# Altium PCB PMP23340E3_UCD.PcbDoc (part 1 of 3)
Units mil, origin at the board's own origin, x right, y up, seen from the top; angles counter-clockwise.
Board outline 2299.21 x 1157.48 mil, 14 copper layers (Top Layer, Layer 1, Layer 2, Layer 3, Layer 4, Layer 5, Layer 6, Layer 7, Layer 8, Layer 9, Layer 10, Layer 11, Layer 12, Bottom Layer), stack 130 mil thick; 242 components, 71 nets, 1021 pads, 321 vias.
Unrouted connection lines stored in the file: 1.
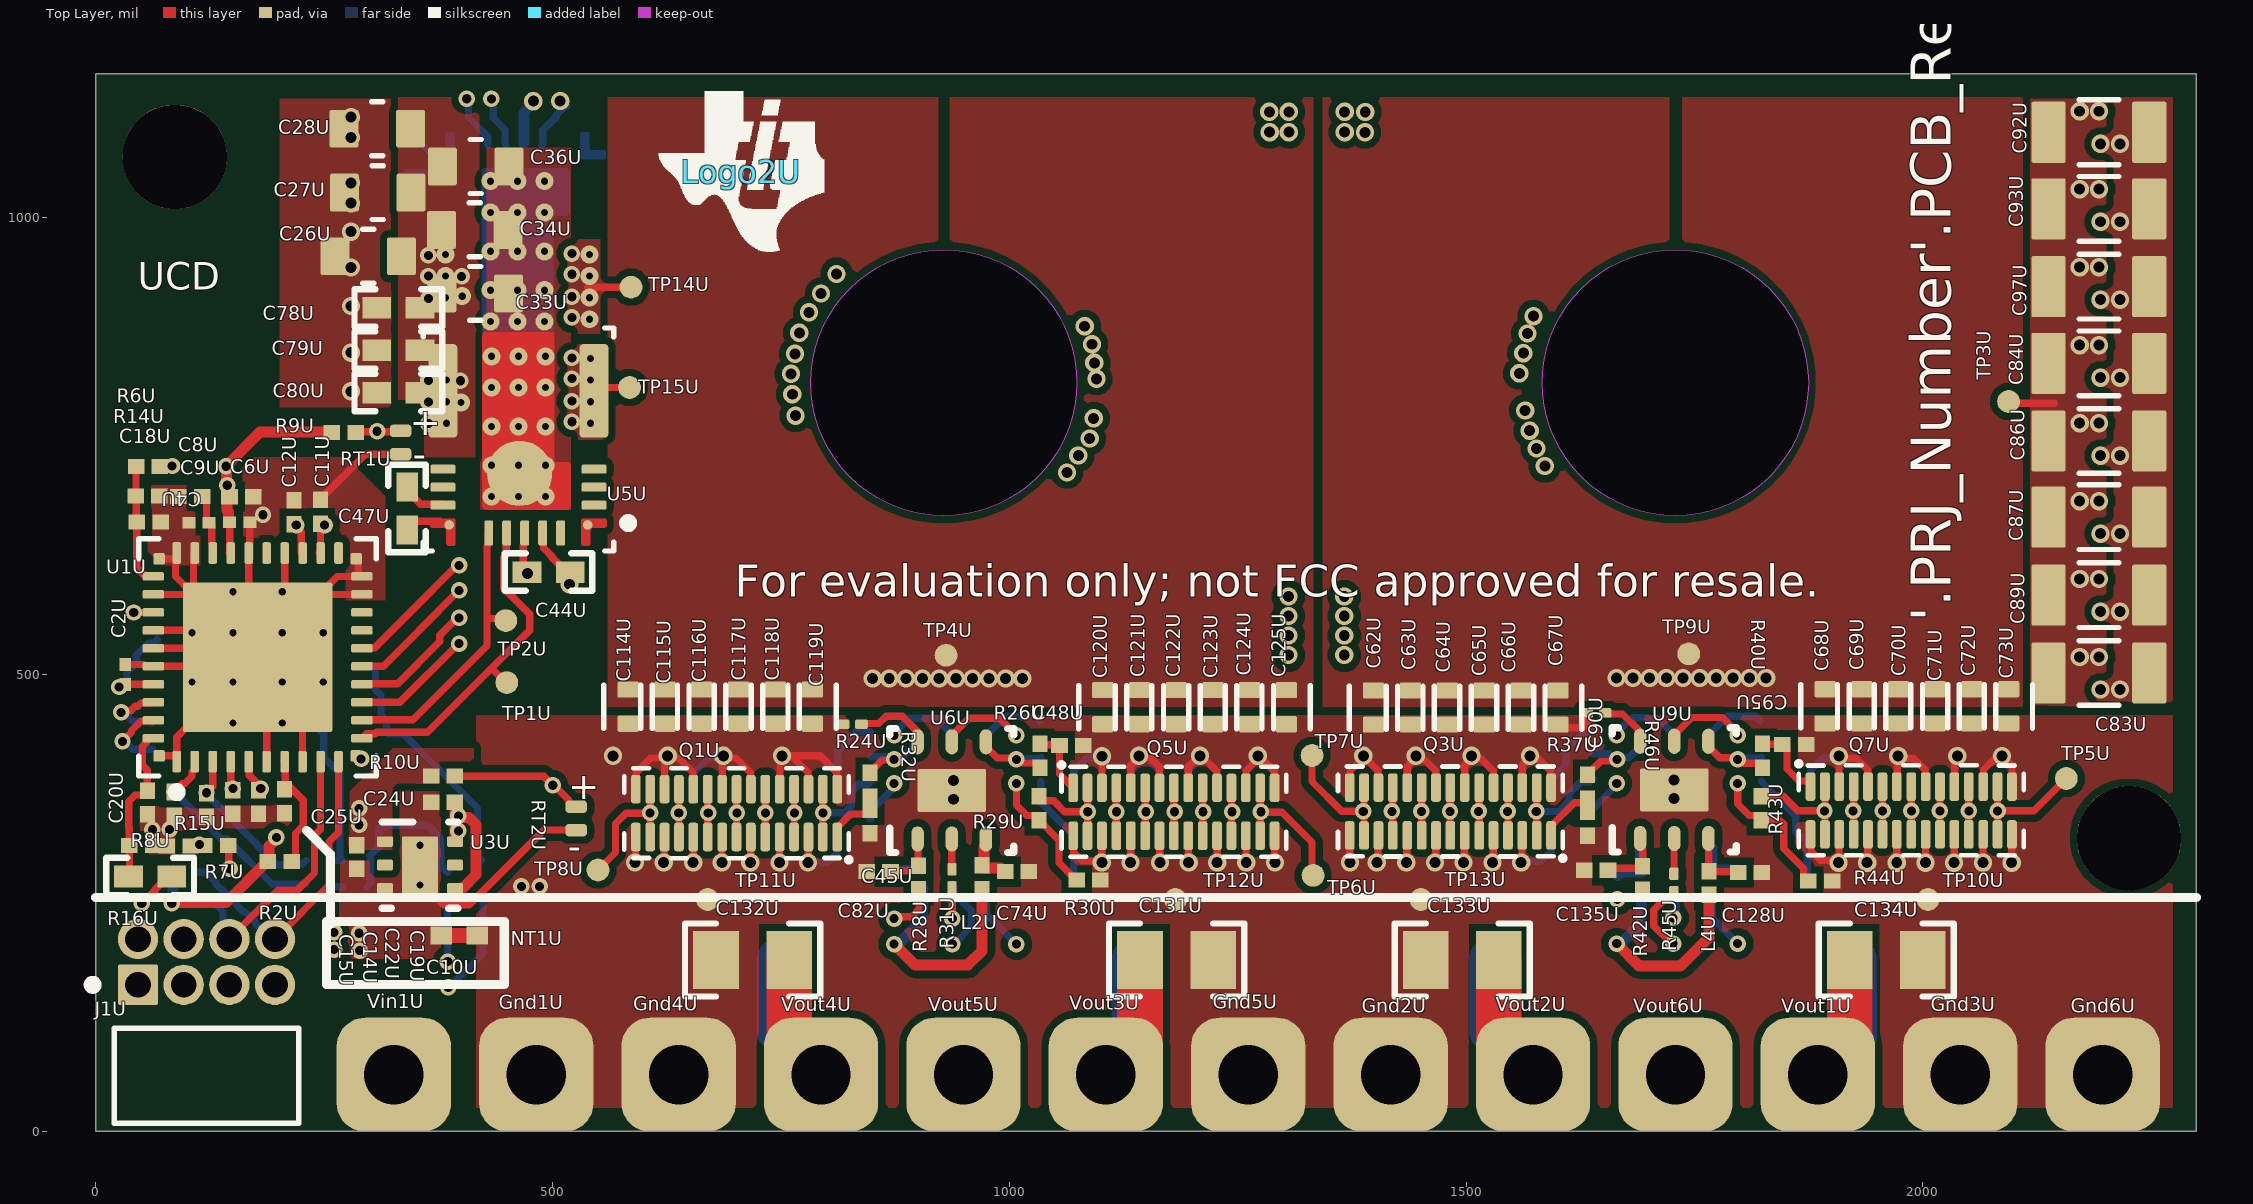
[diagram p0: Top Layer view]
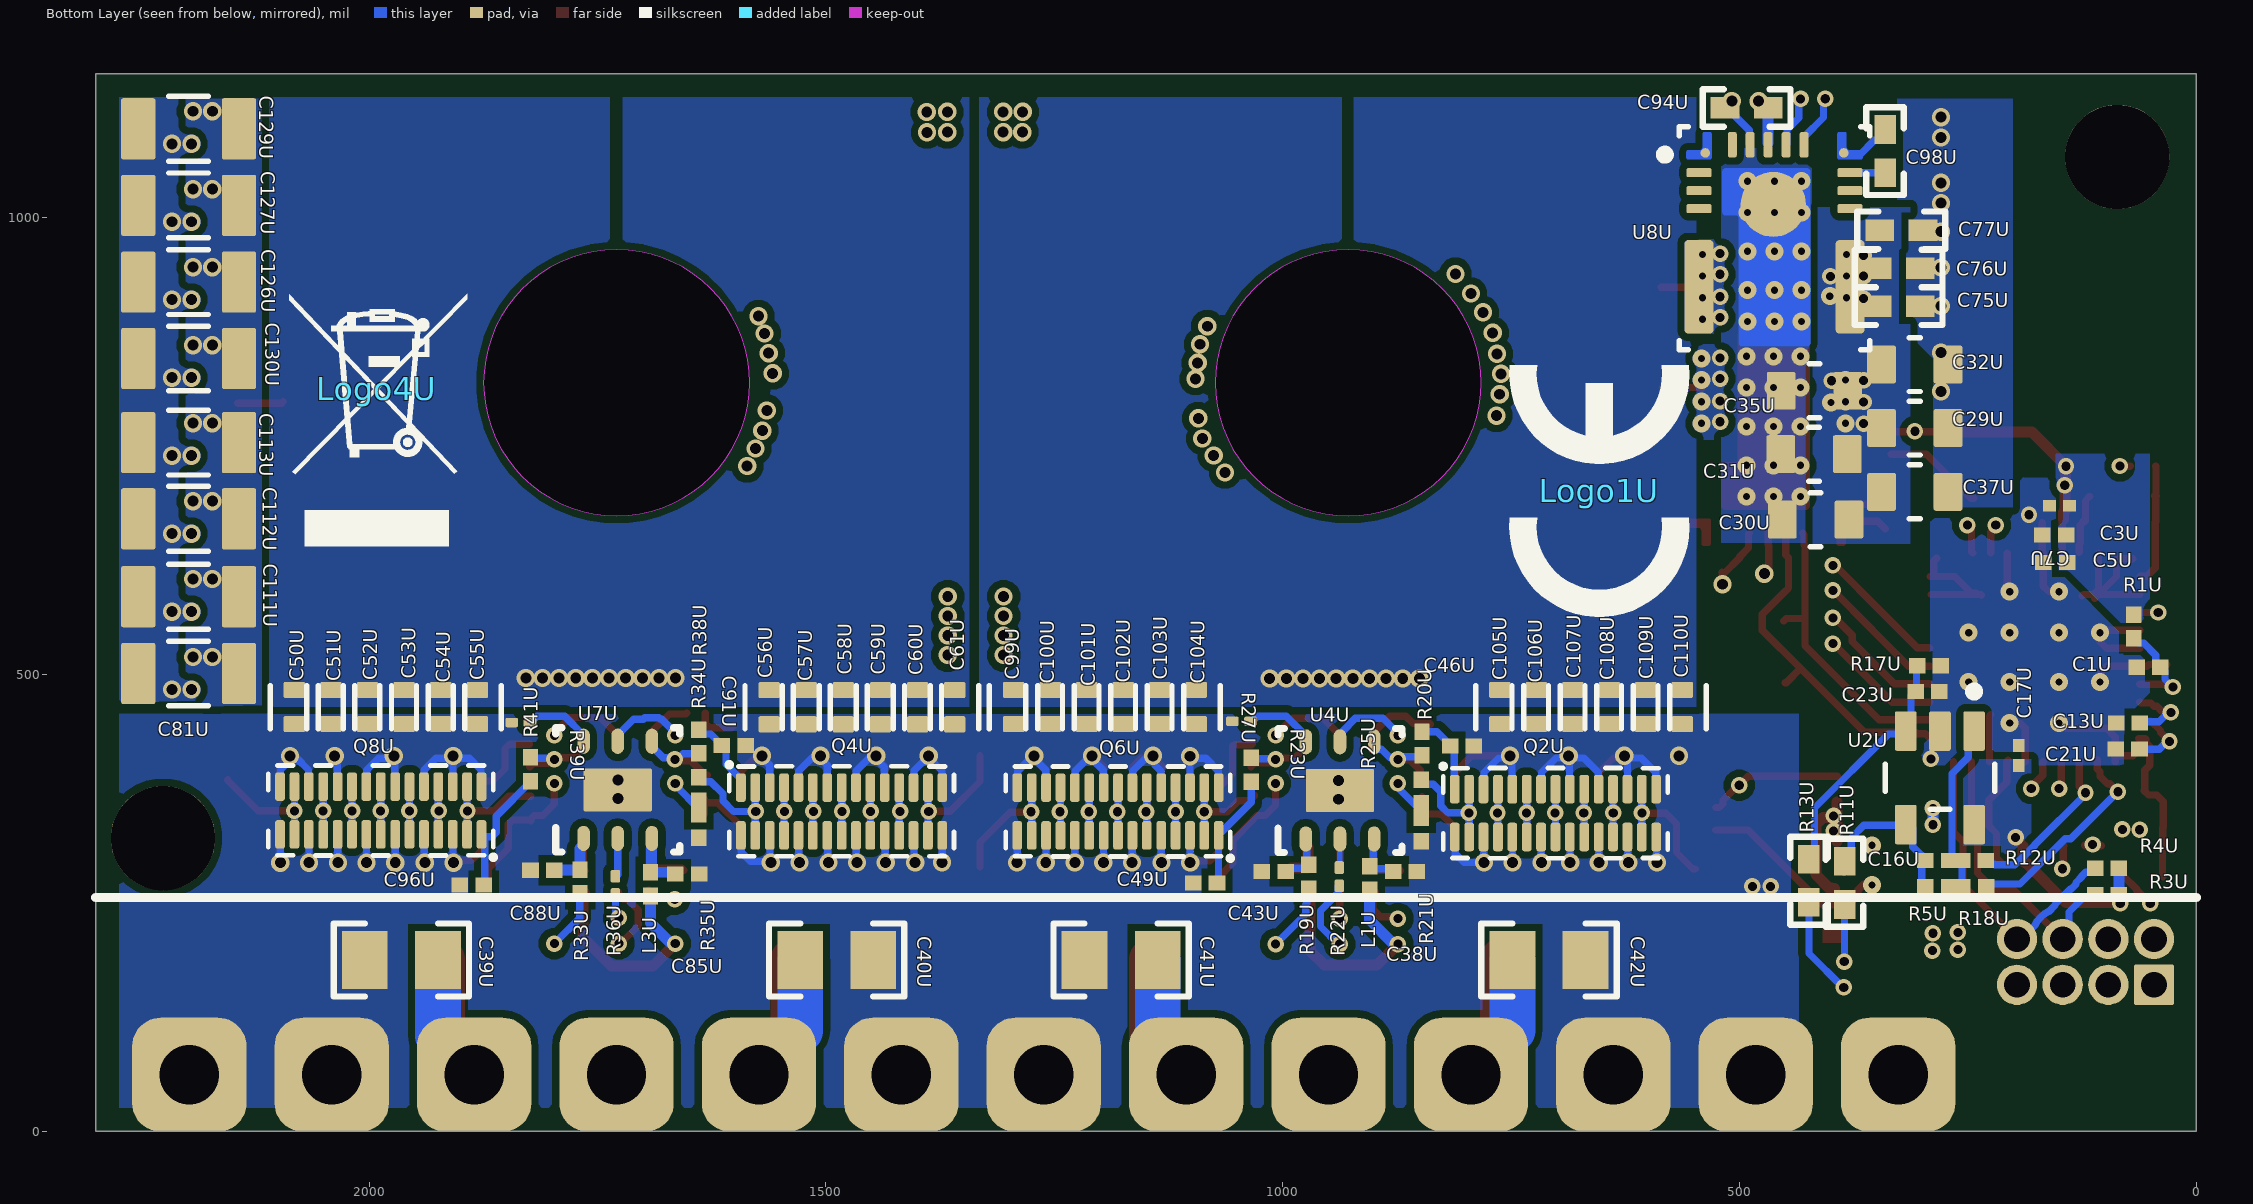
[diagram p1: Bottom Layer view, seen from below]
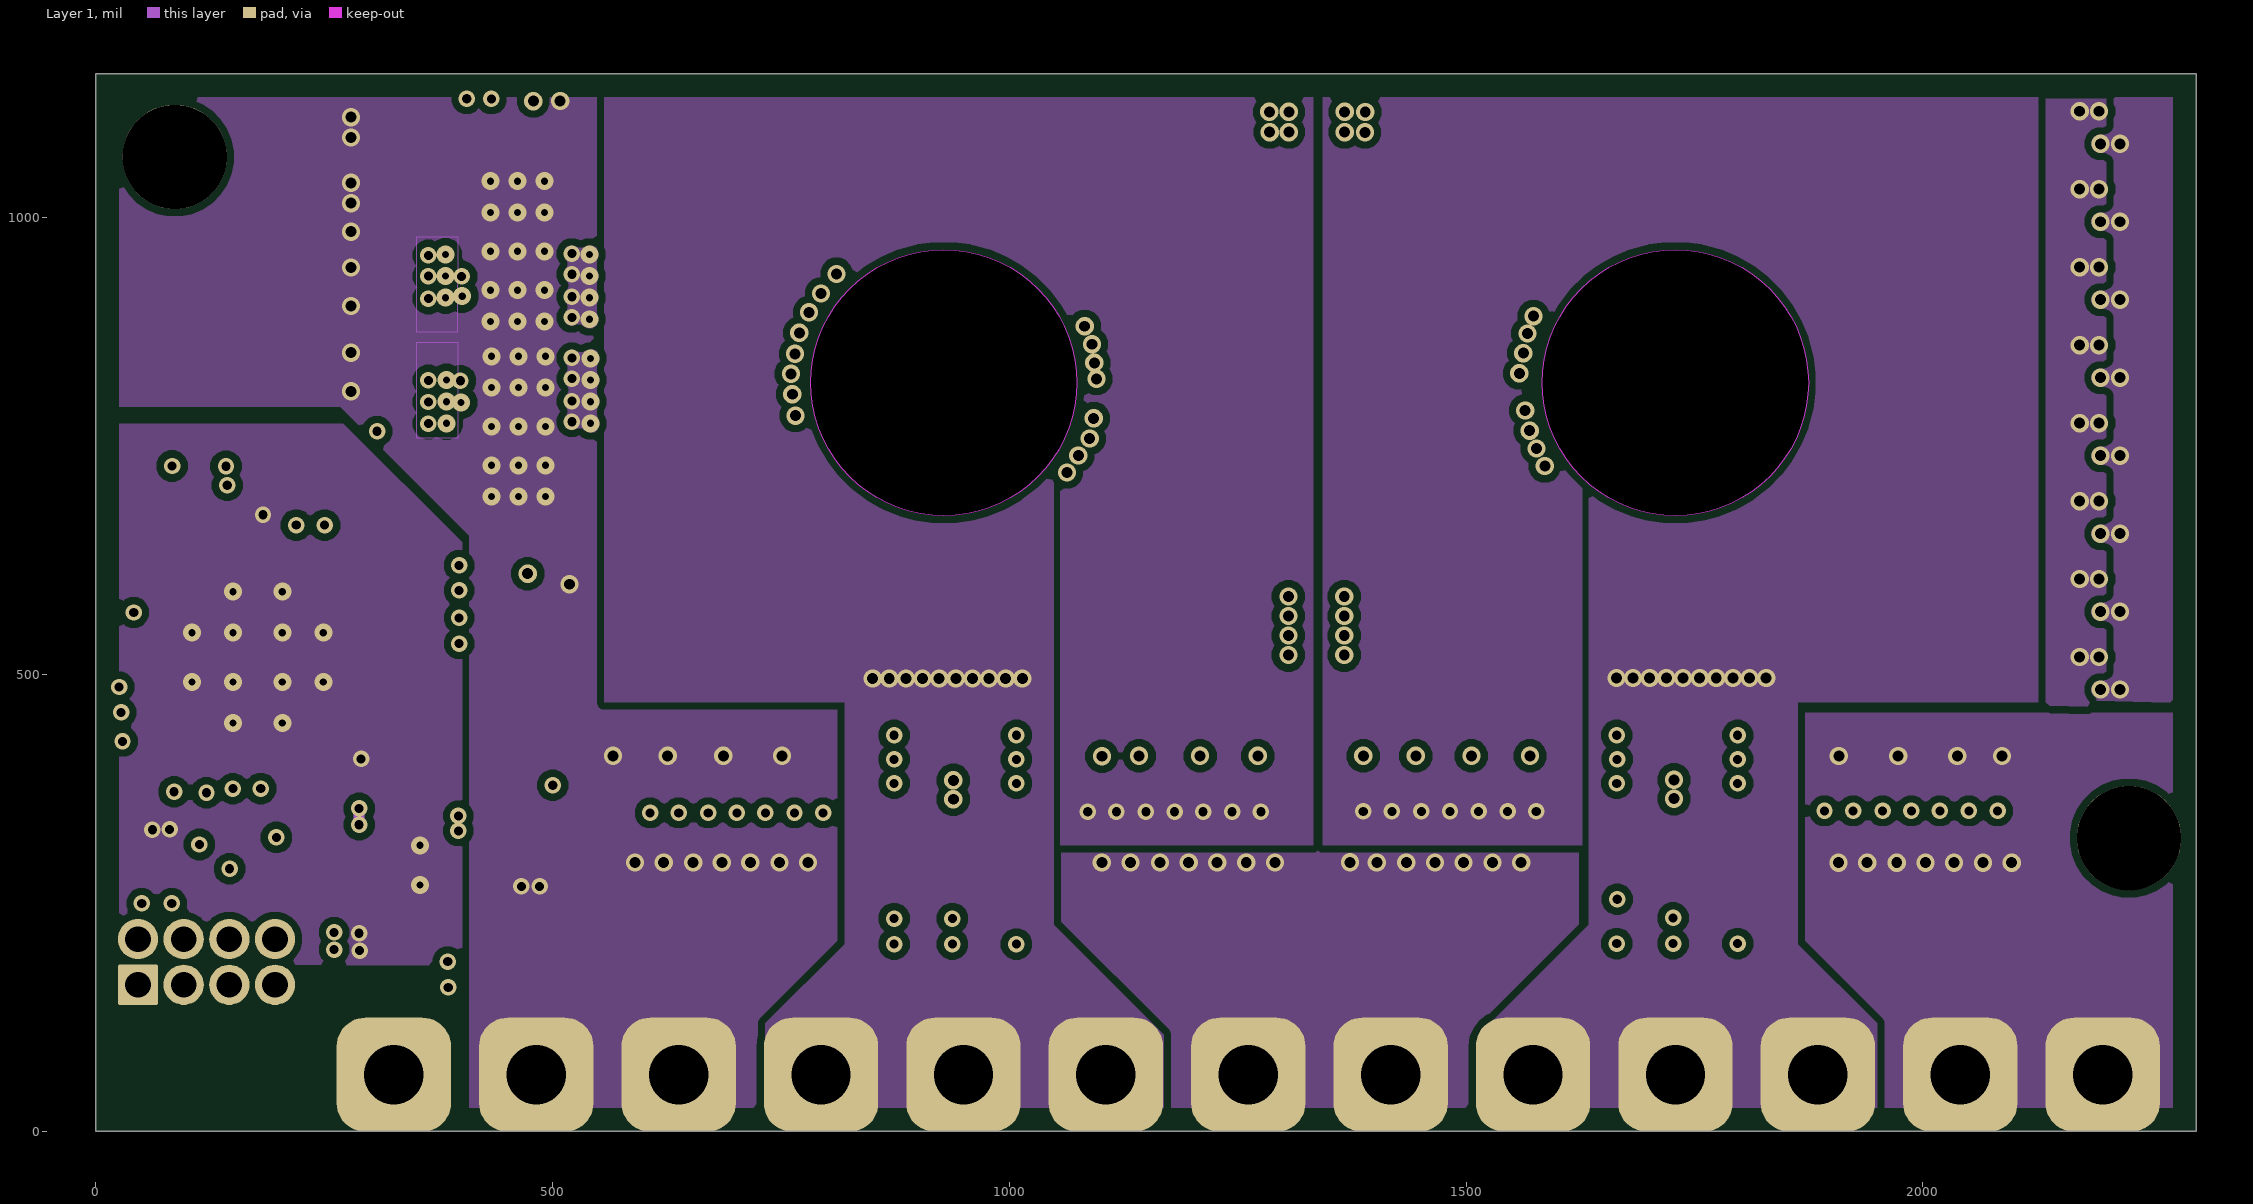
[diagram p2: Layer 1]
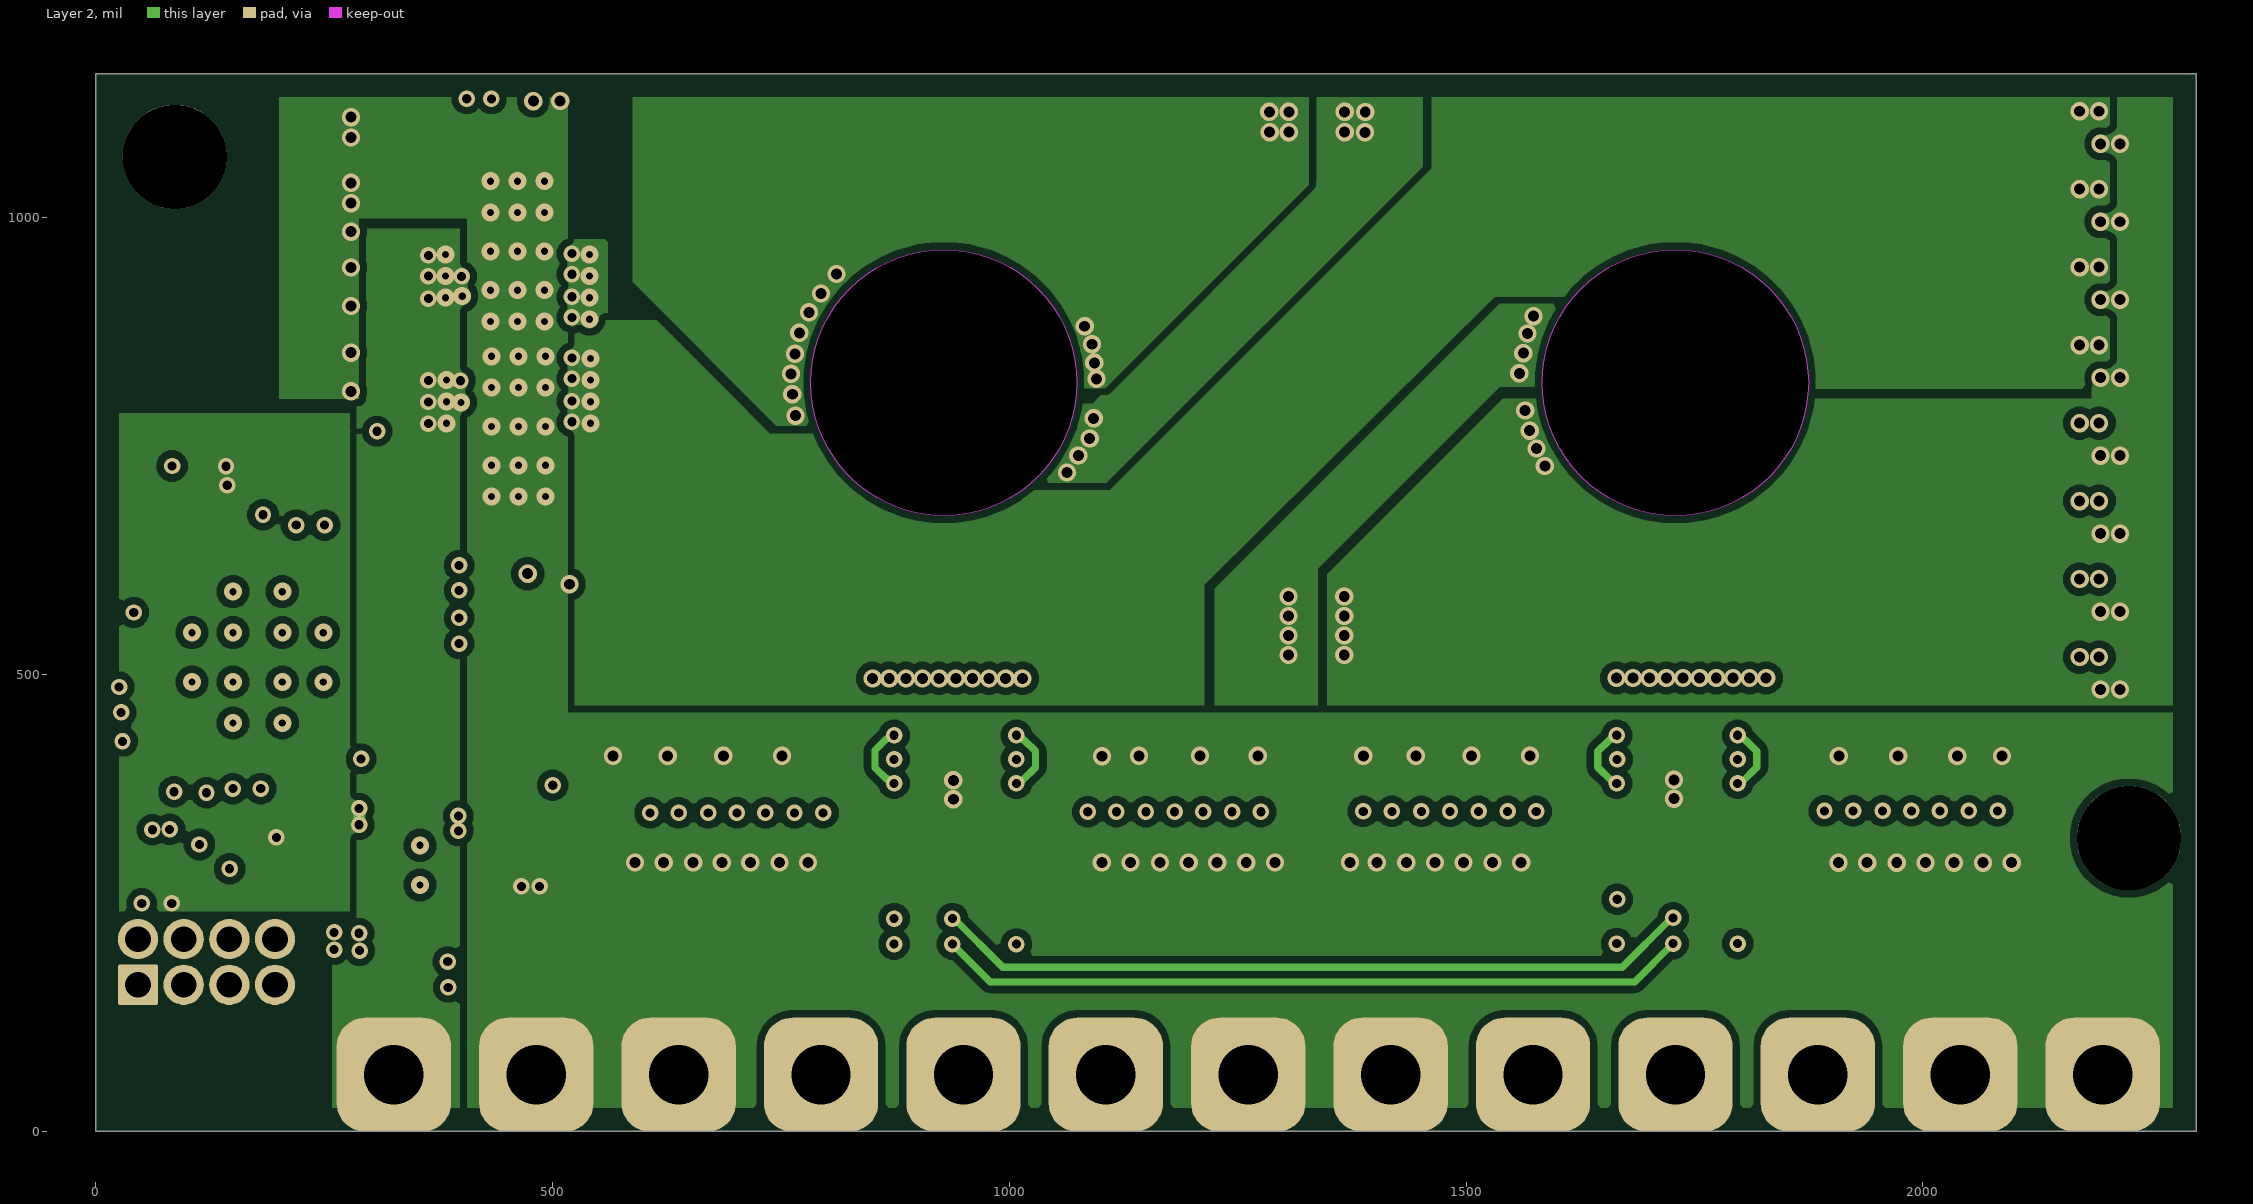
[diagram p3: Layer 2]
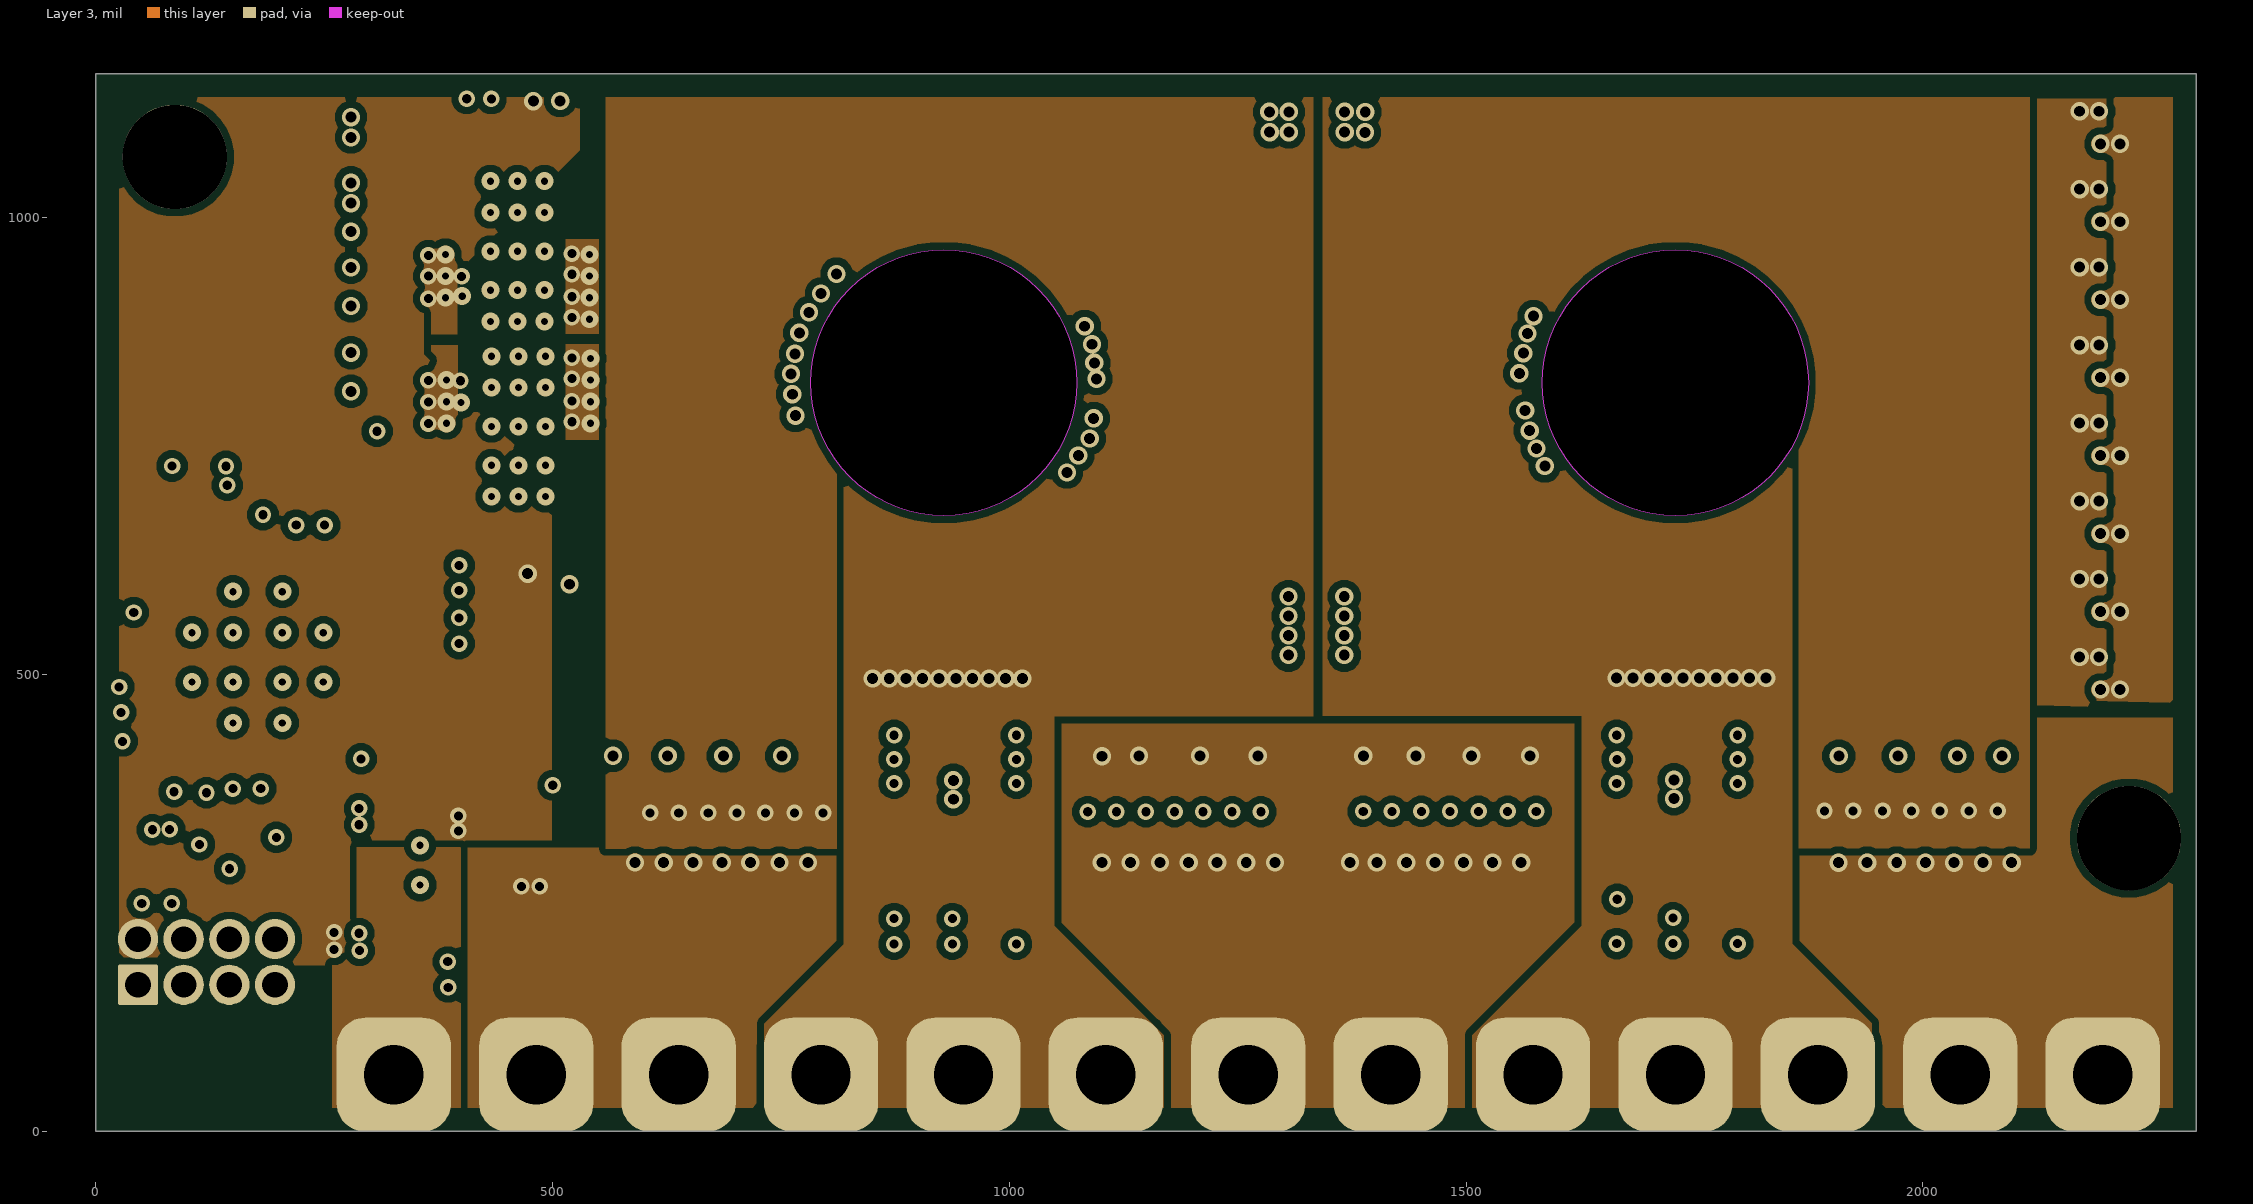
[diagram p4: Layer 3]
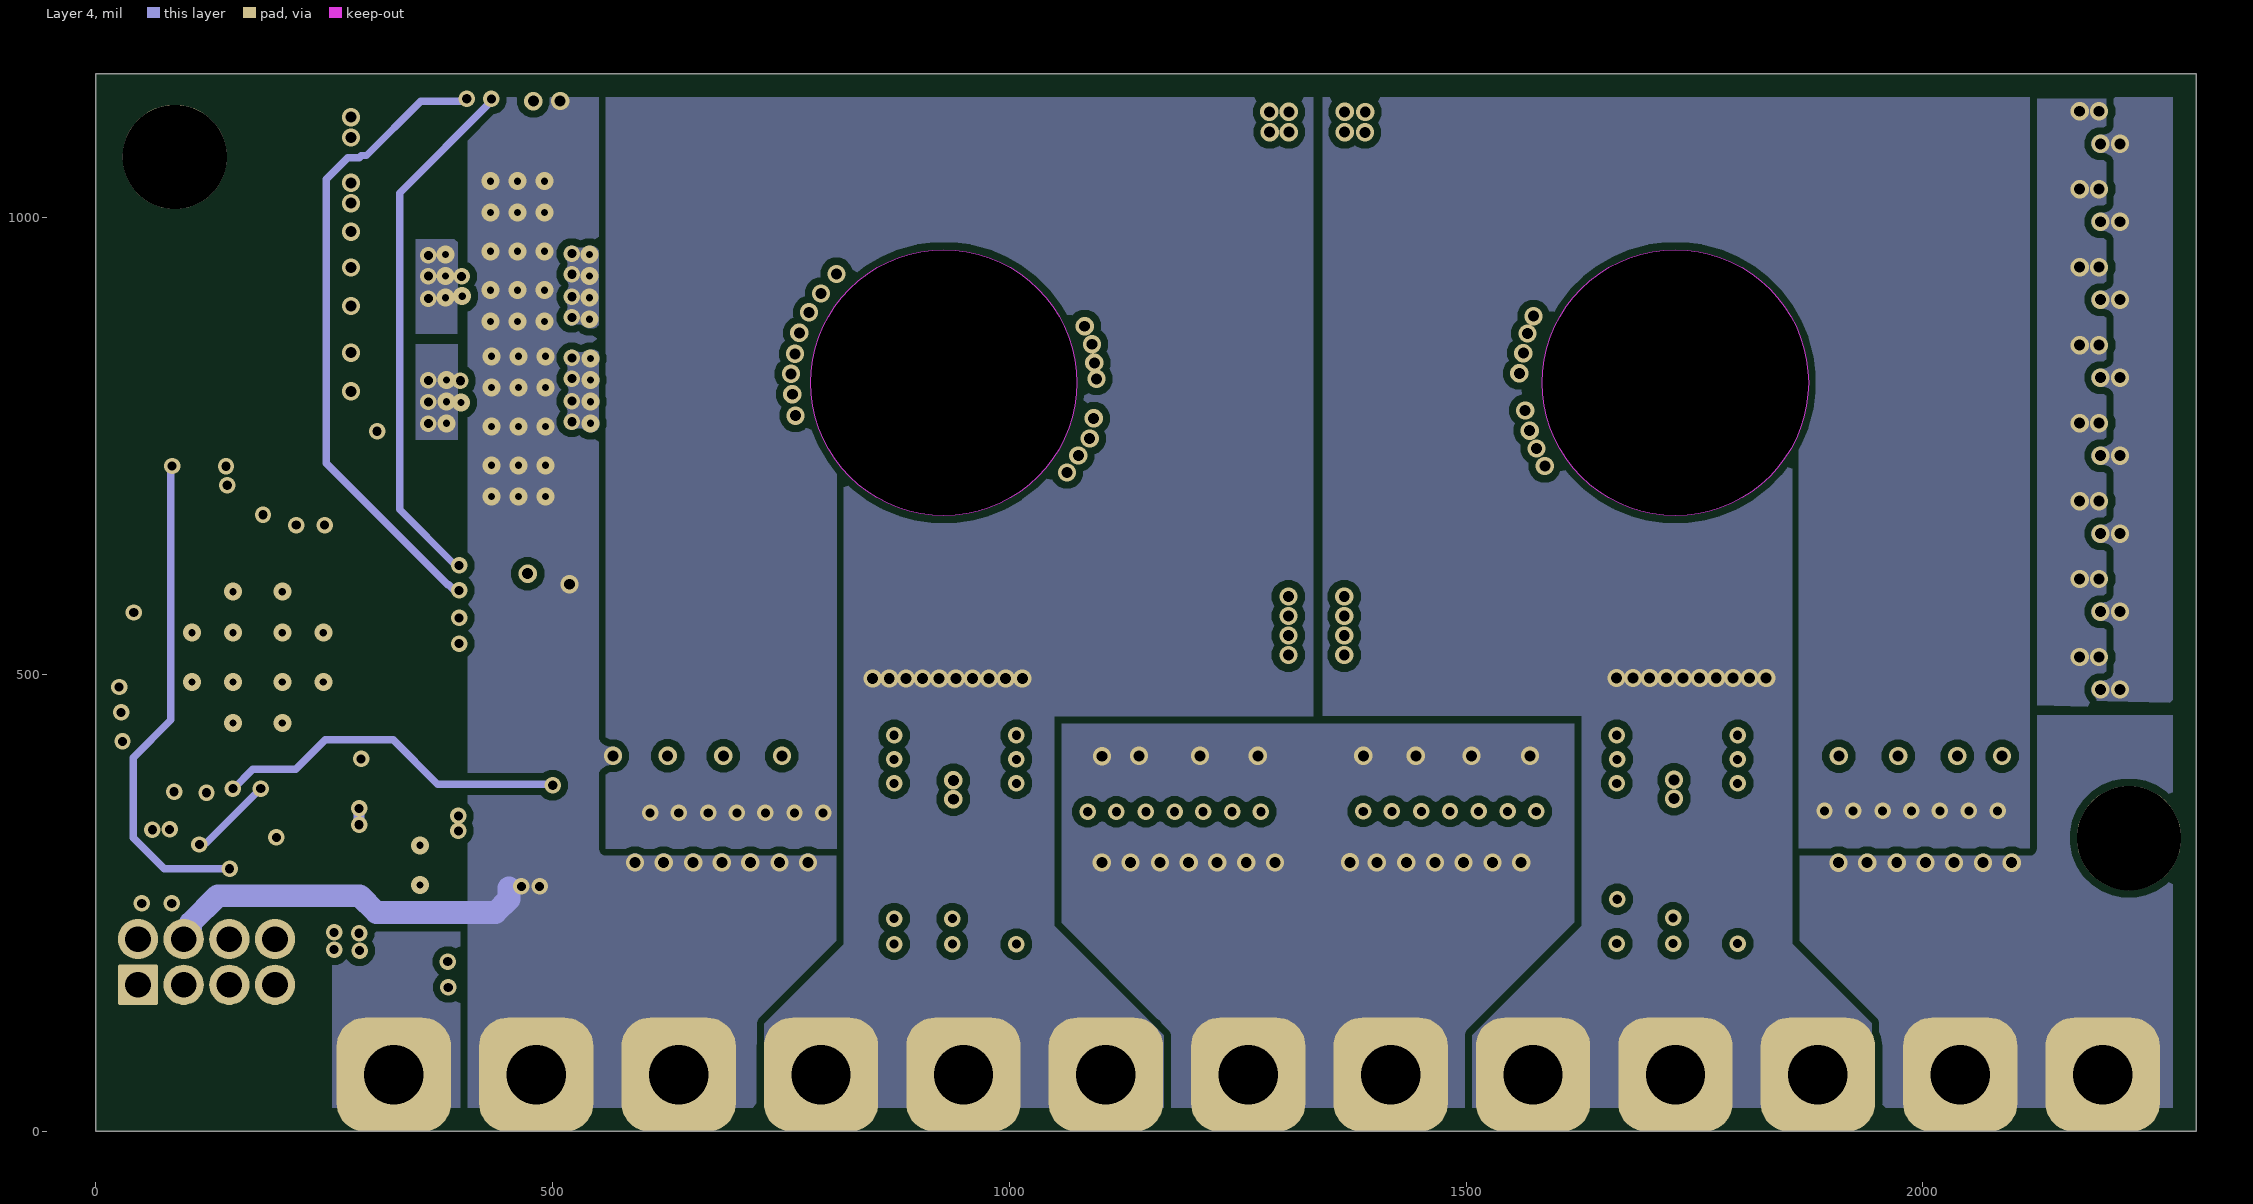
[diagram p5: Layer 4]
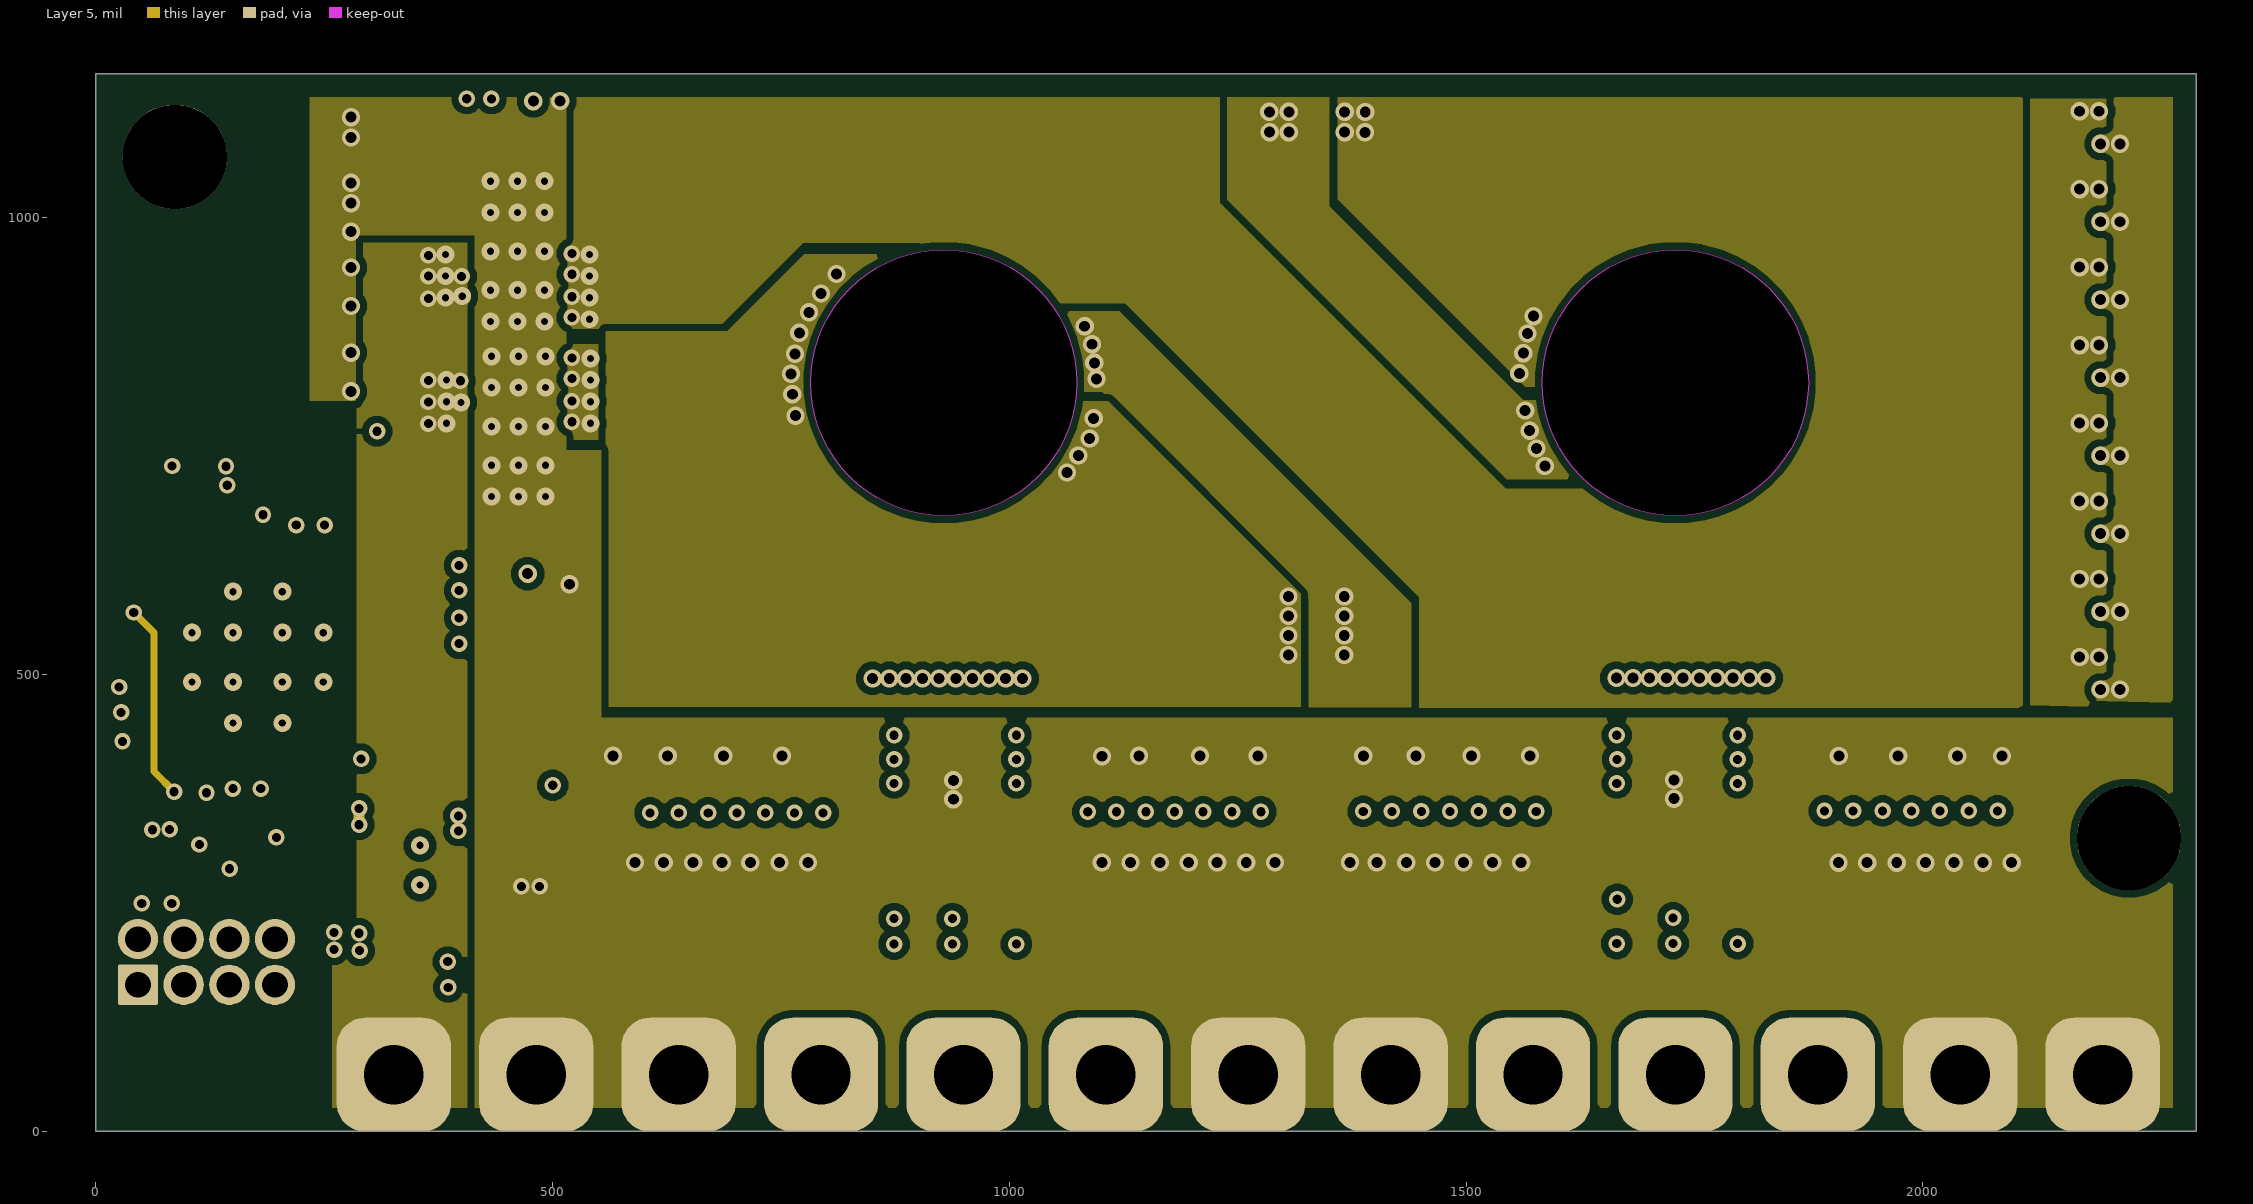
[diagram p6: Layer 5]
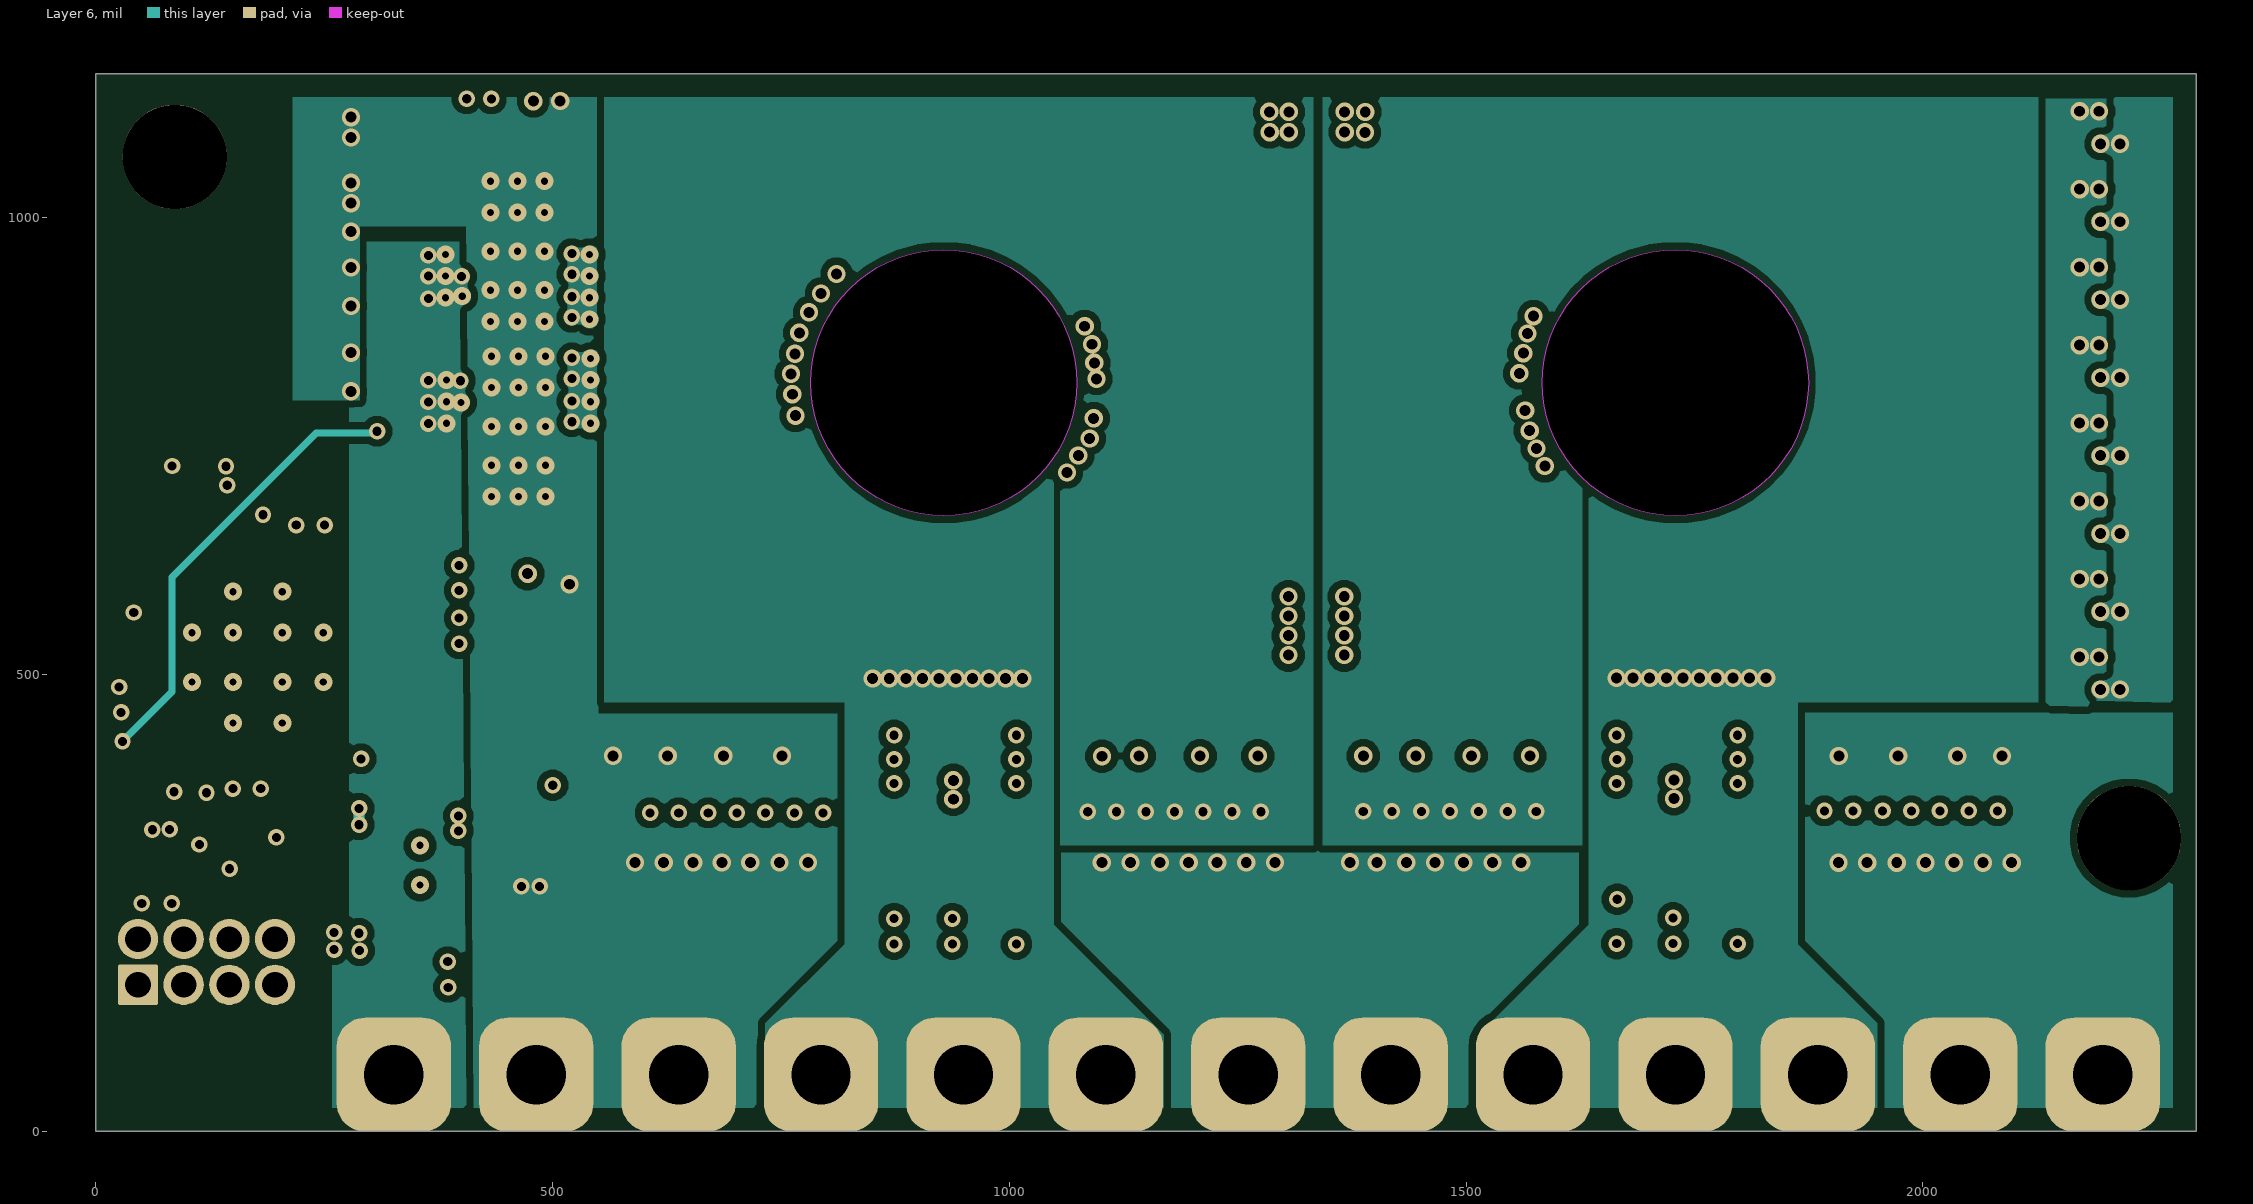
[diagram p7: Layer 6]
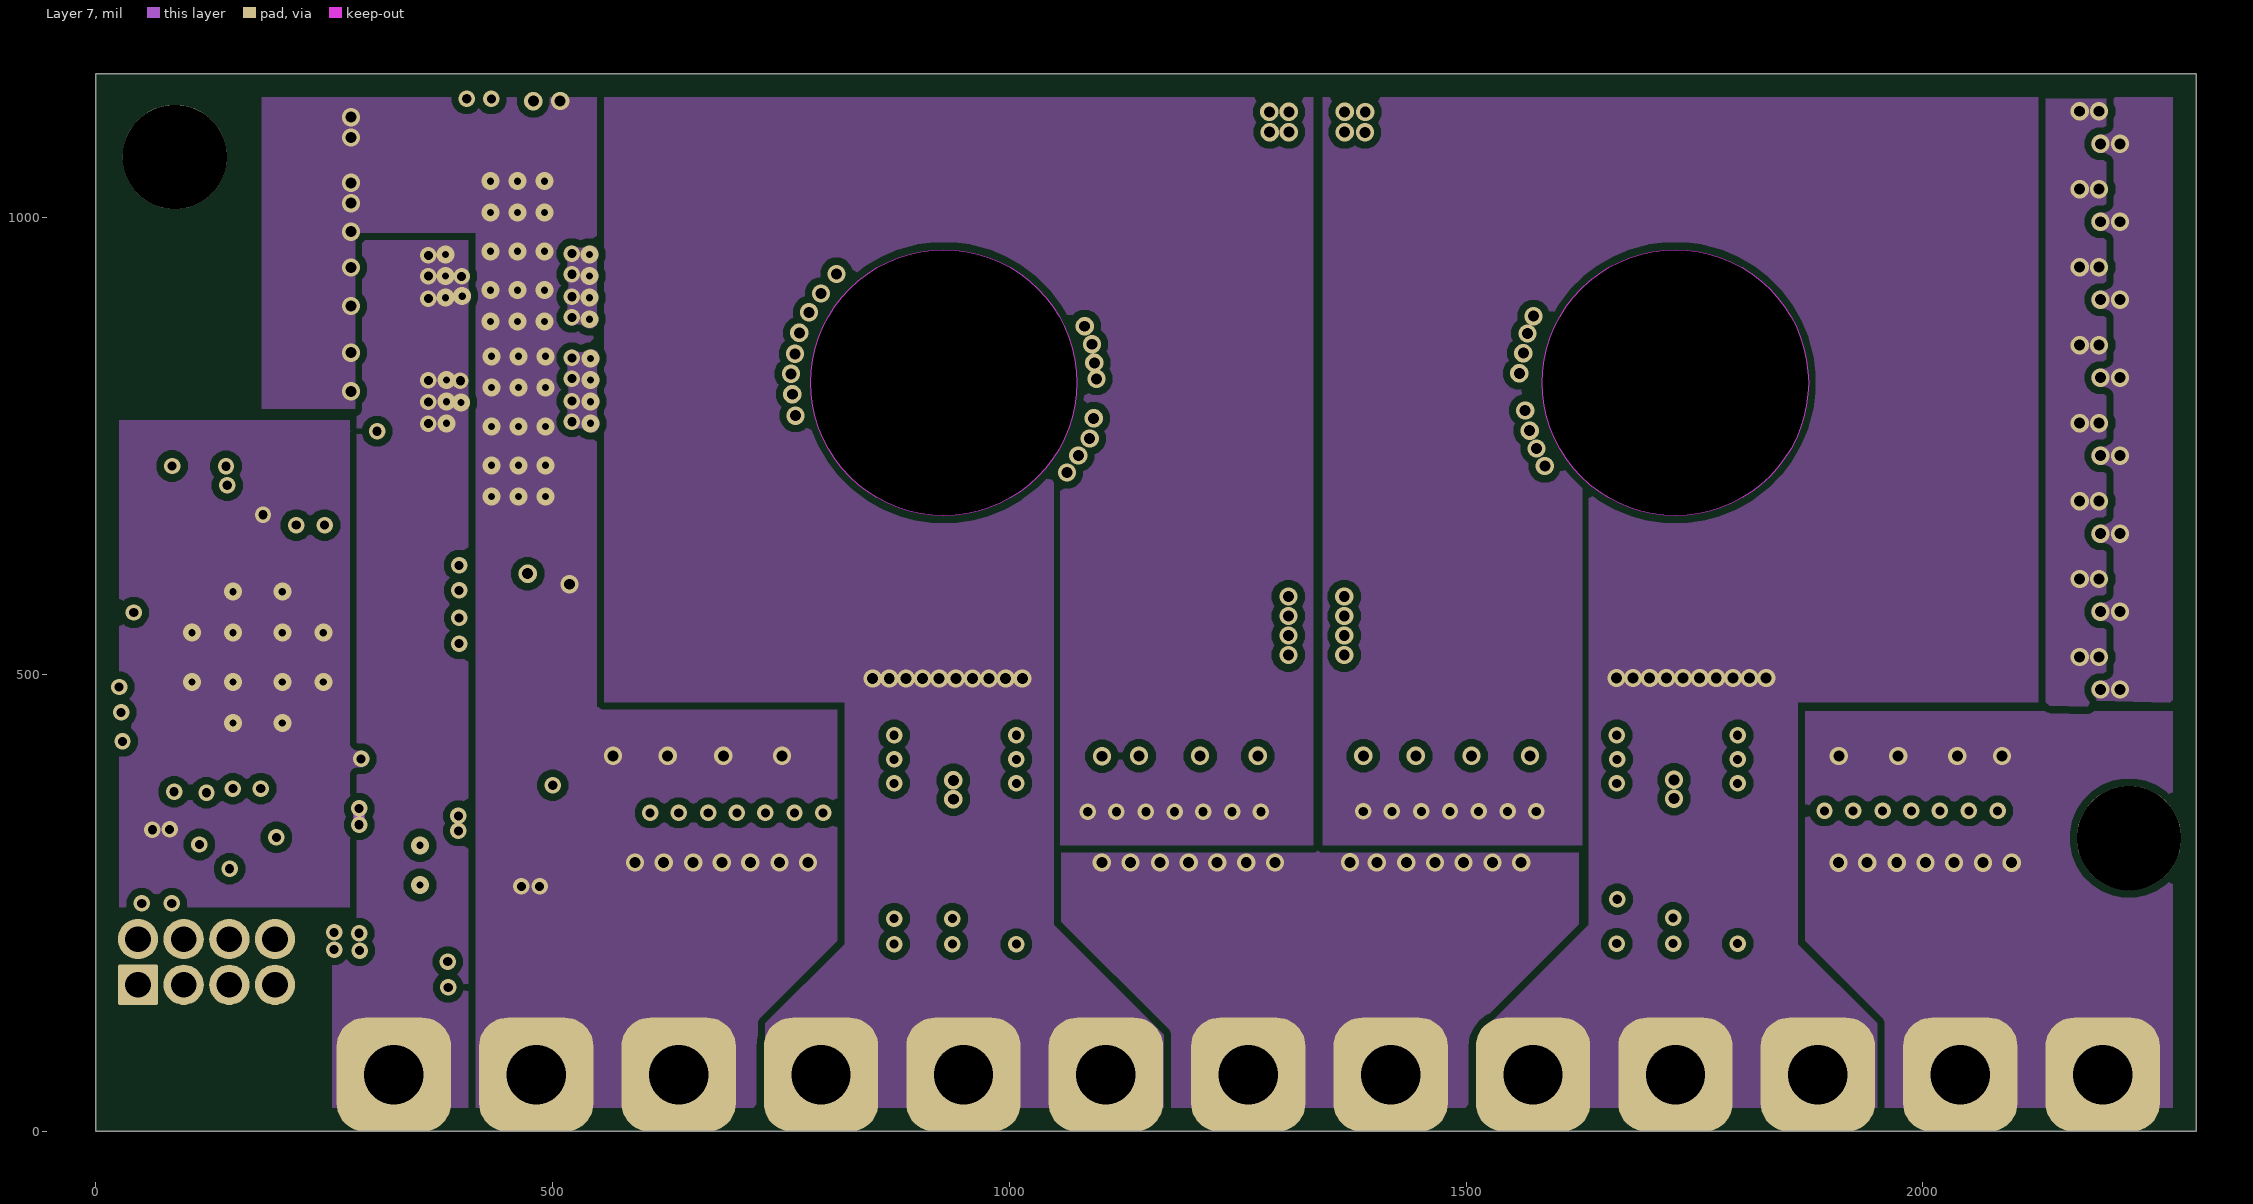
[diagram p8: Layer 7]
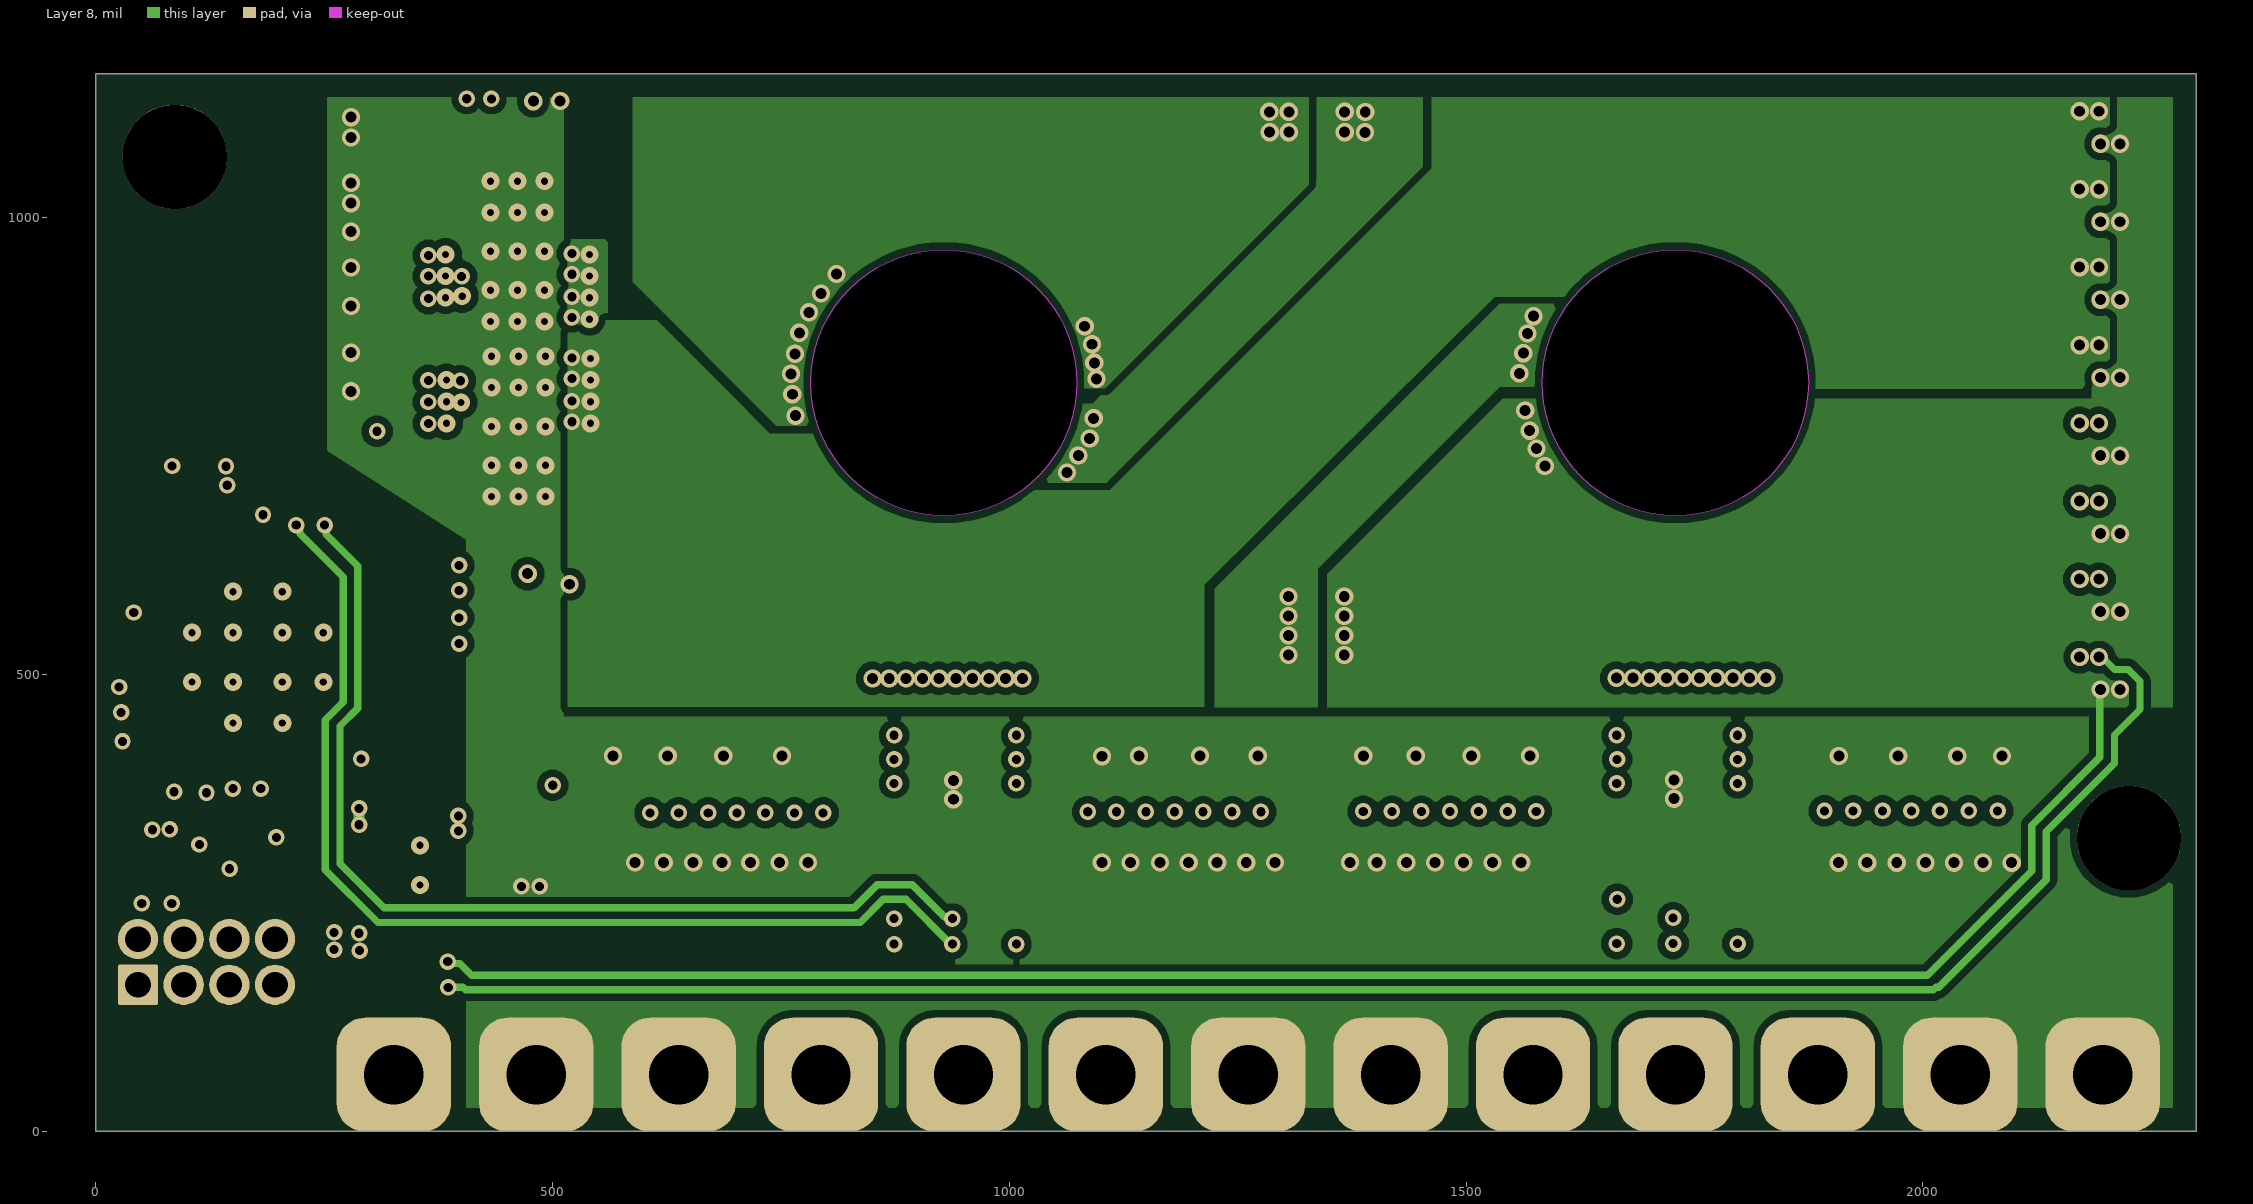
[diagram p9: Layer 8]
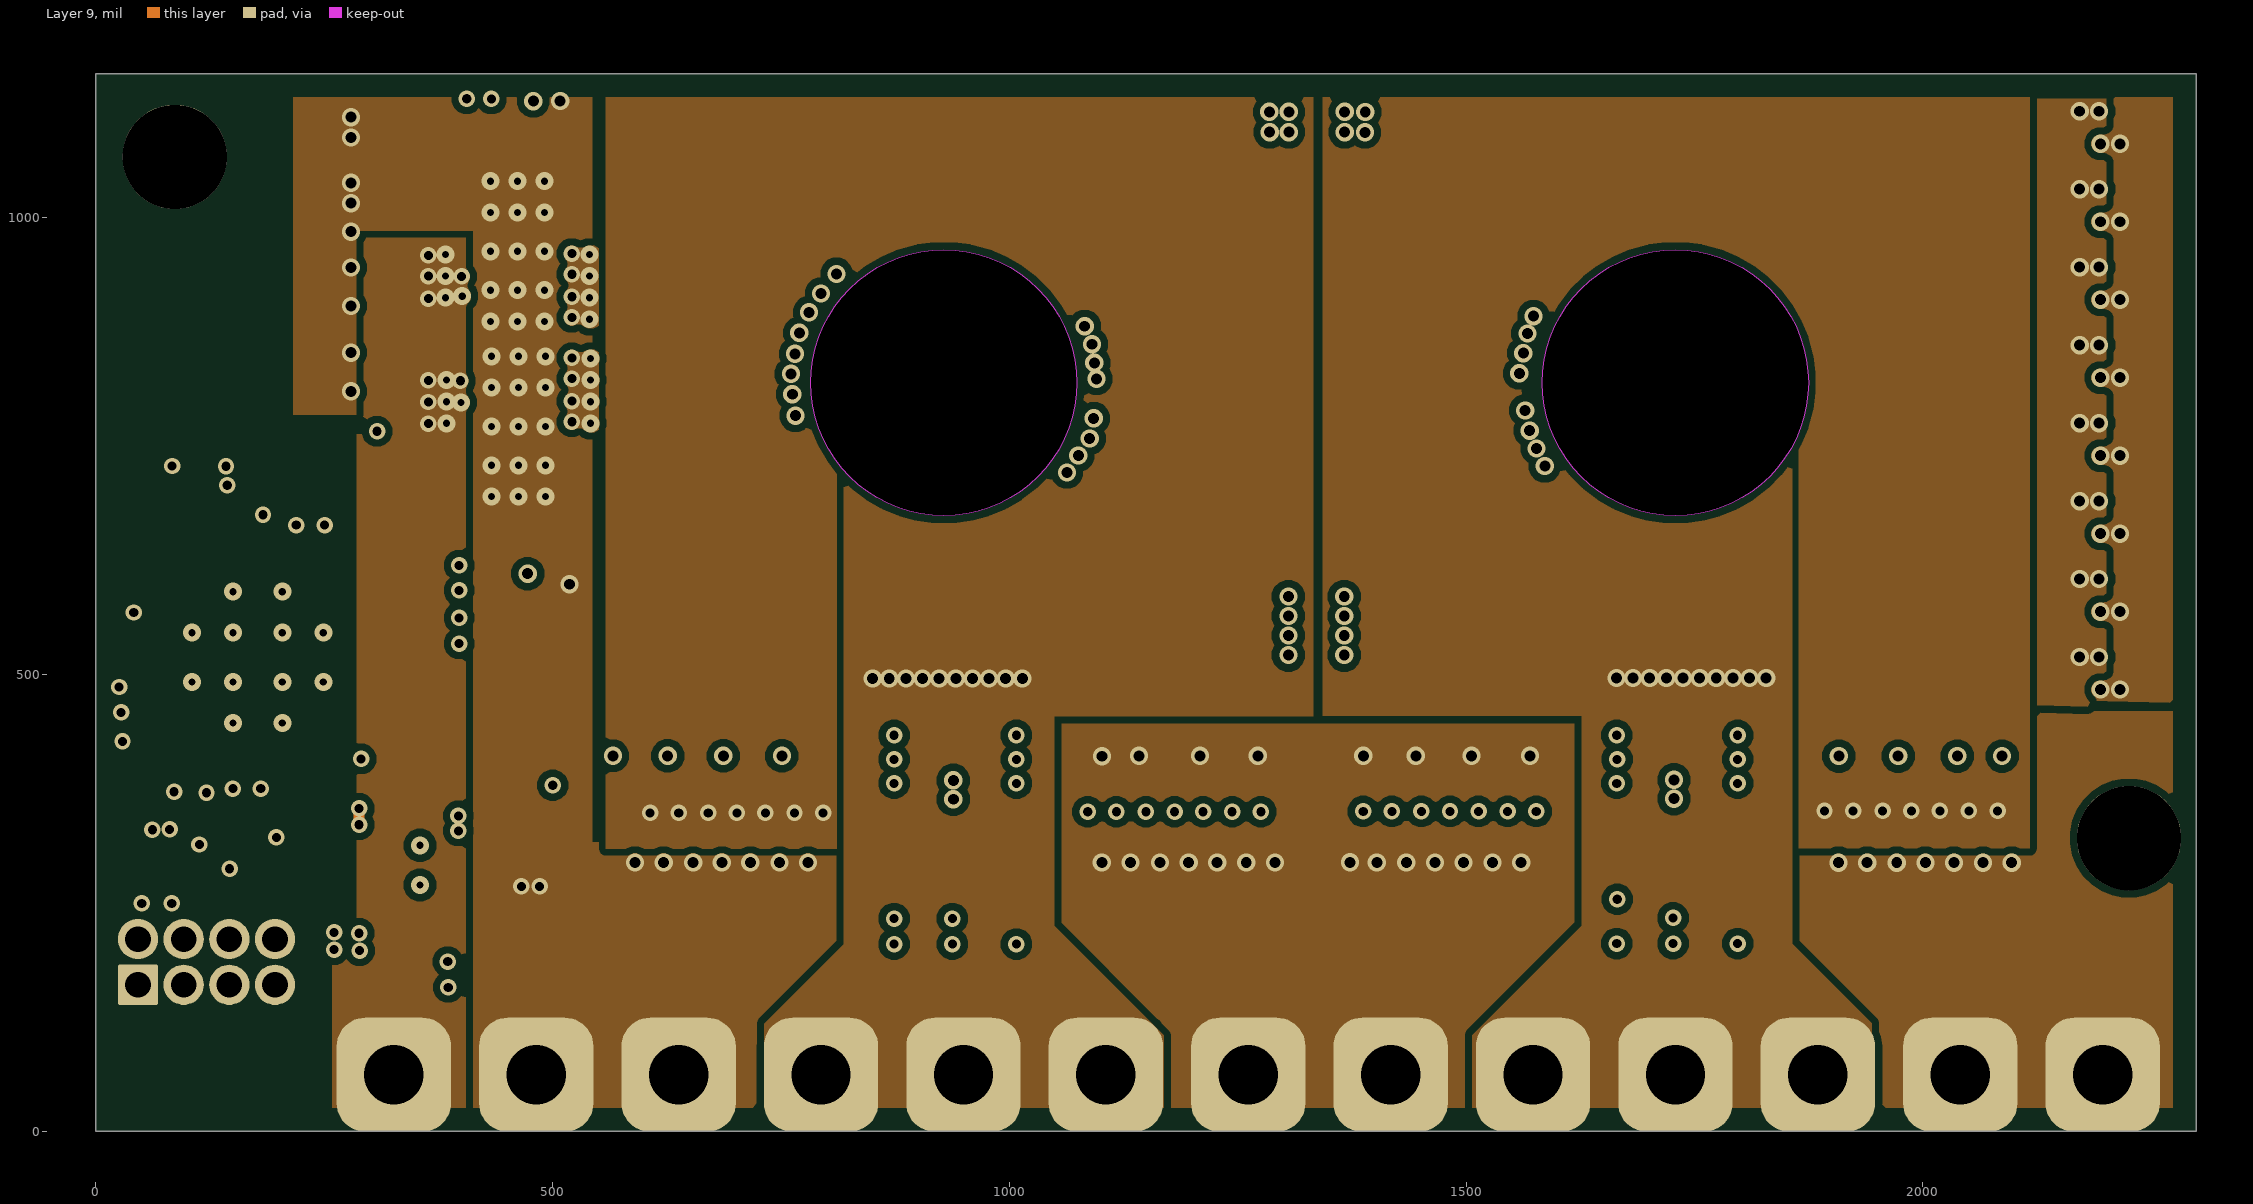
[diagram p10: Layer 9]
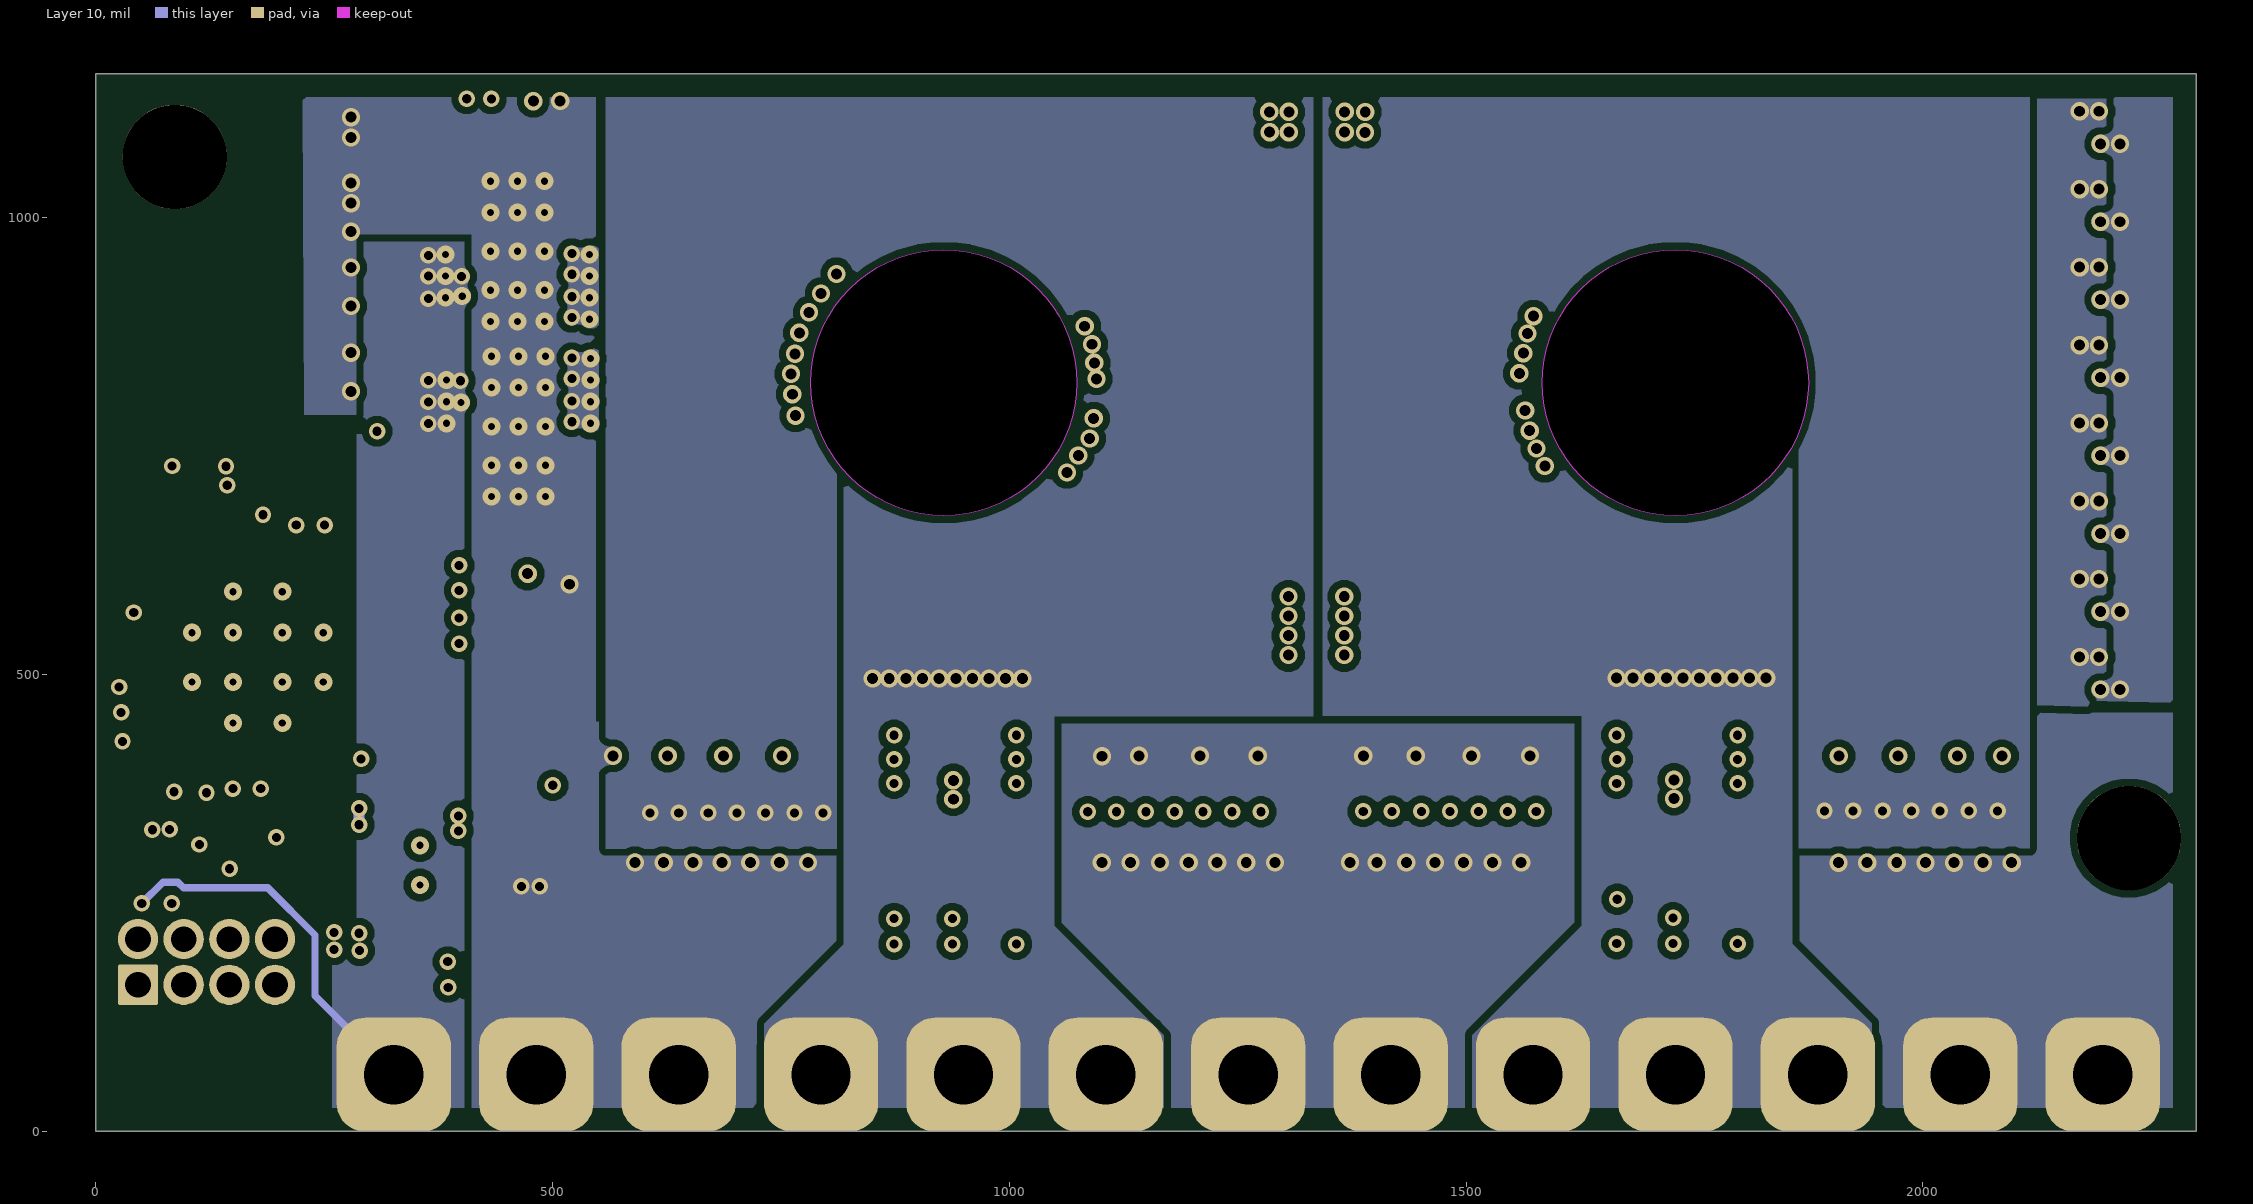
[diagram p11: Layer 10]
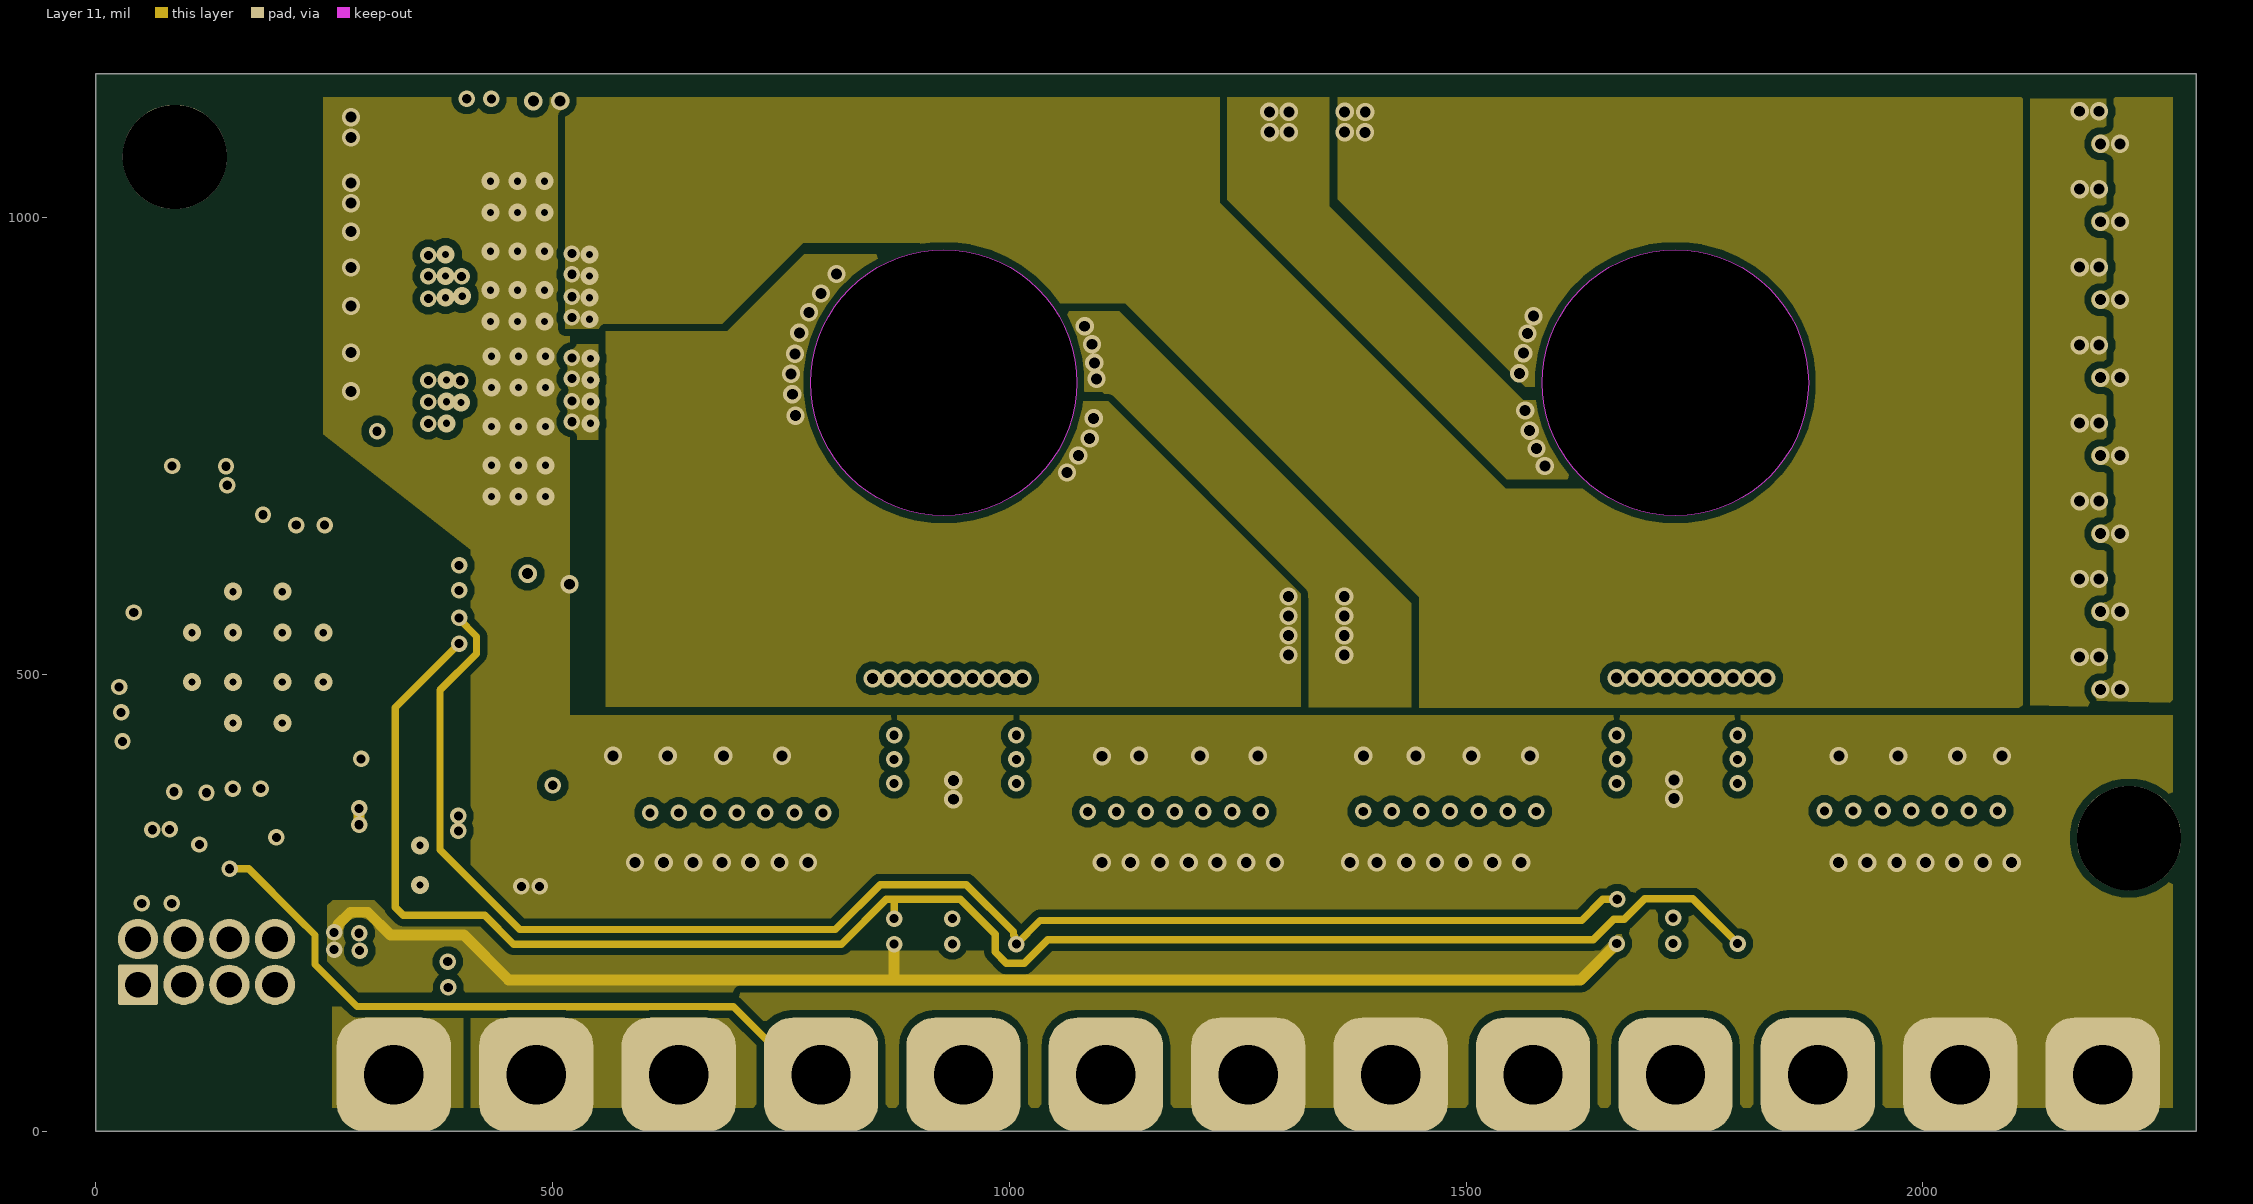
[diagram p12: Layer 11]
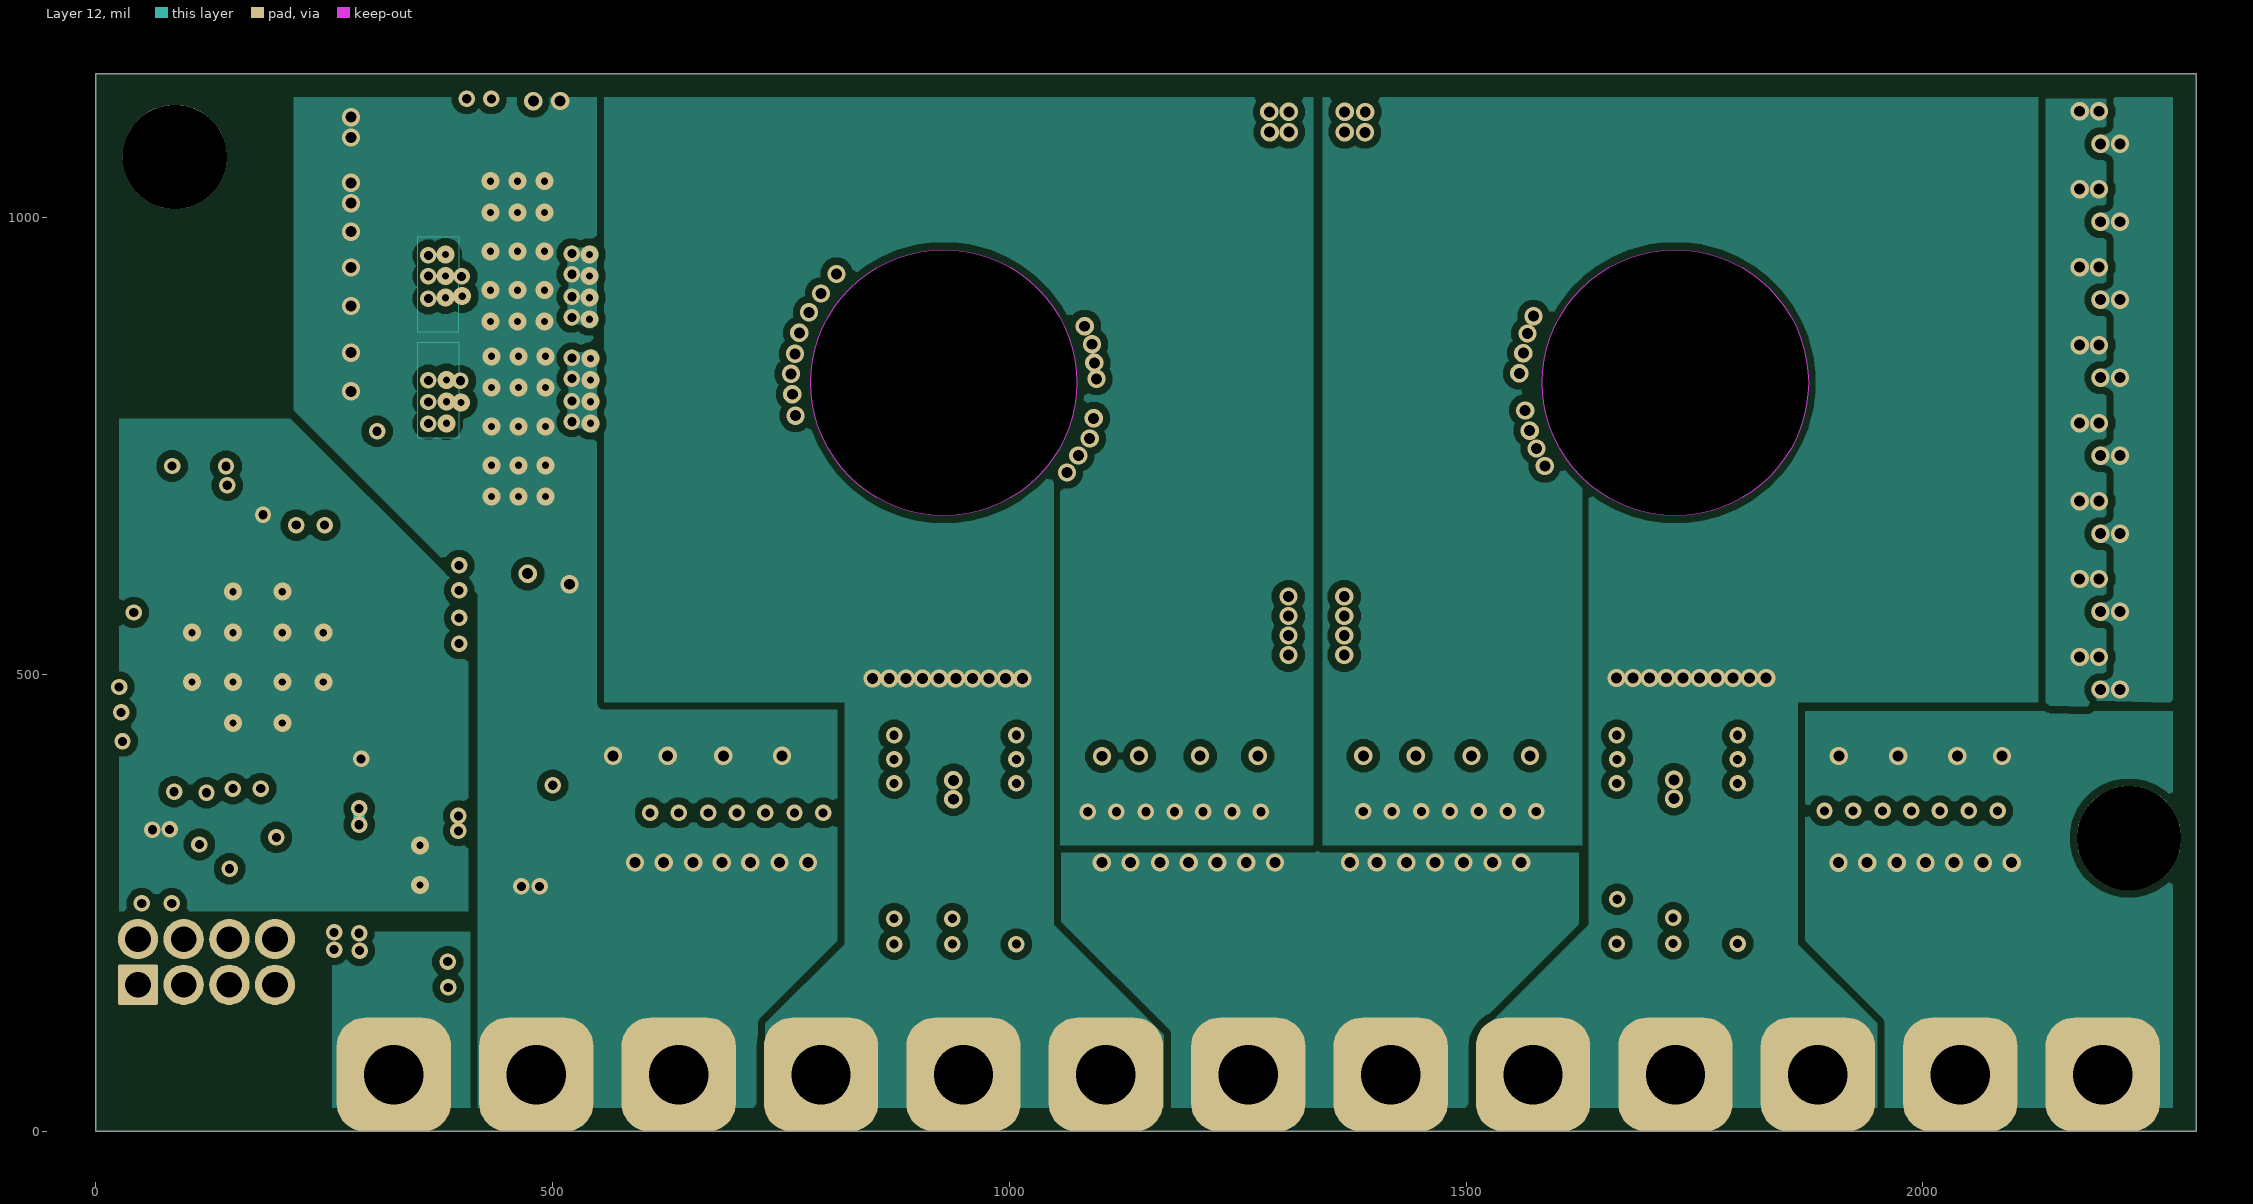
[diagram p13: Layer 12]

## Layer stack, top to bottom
Top Solder: solder mask 0.4, Solder Resist, Dk 3.5
Top Layer: signal copper 2.4
Dielectric 1: prepreg 8, FR-4 High Tg, Dk 3.9
Layer 1: signal copper 3.6
Dielectric 2: core 6, FR-4 High Tg, Dk 3.9
Layer 2: signal copper 3.6
Dielectric 3: prepreg 6, FR-4 High Tg, Dk 3.9
Layer 3: signal copper 3.6
Dielectric 4: core 6, FR-4 High Tg, Dk 3.9
Layer 4: signal copper 3.6
Dielectric 5: prepreg 6, FR-4 High Tg, Dk 3.9
Layer 5: signal copper 3.6
Dielectric 6: core 6, FR-4 High Tg, Dk 3.9
Layer 6: signal copper 3.6
Dielectric 7: prepreg 6, FR-4 High Tg, Dk 3.9
Layer 7: signal copper 3.6
Dielectric 8: core 6, FR-4 High Tg, Dk 3.9
Layer 8: signal copper 3.6
Dielectric 9: prepreg 6, FR-4 High Tg, Dk 3.9
Layer 9: signal copper 3.6
Dielectric 10: core 6, FR-4 High Tg, Dk 3.9
Layer 10: signal copper 3.6
Dielectric 11: prepreg 6, FR-4 High Tg, Dk 3.9
Layer 11: signal copper 3.6
Dielectric 12: core 6, FR-4 High Tg, Dk 3.9
Layer 12: signal copper 3.6
Dielectric 13: prepreg 8, FR-4 High Tg, Dk 3.9
Bottom Layer: signal copper 2.4
Bottom Solder: solder mask 0.4, Solder Resist, Dk 3.5

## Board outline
0,0 2299.21,0 2299.21,1157.48 0,1157.48
cut-out: 928.35,673.7 cw(c928.35,819.37) 782.68,819.37 cw(c928.35,819.37) 928.35,965.04 cw(c928.35,819.37) 1074.02,819.37 cw(c928.35,819.37)
cut-out: 1729.14,673.7 cw(c1729.14,819.37) 1583.47,819.37 cw(c1729.14,819.37) 1729.14,965.04 cw(c1729.14,819.37) 1874.81,819.37 cw(c1729.14,819.37)

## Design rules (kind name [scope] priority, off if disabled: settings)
AcuteAngle [All] p1: minimum=4.50000000000000E+0001 checktracksonly=FALSE
AssemblyTestPointUsage [All] p1: valid=2
BoardOutlineClearance BoardOutlineClearance_MountingHoles [OnCopper and InComponentClass('Mounting Holes')] p1: gap=39.37 ignorepadtopadclearanceinfootprint=FALSE
BoardOutlineClearance BoardOutlineClearance_Poly [OnCopper and IsPoly] p2: gap=25 ignorepadtopadclearanceinfootprint=FALSE
BoardOutlineClearance [OnCopper and Not InComponentClass('Logo') and not InComponentClass('FiducialMark') and not InRegion(1000,500,4000,800) and not InPoly] p3: gap=25 ignorepadtopadclearanceinfootprint=FALSE except(10: THPad-OutlineEdge THPad-CutoutEdge Via-OutlineEdge Via-CutoutEdge)
Clearance Clearance_Keepouts [((IsTrack Or IsArc) And Not InPoly) And IsFree and IsKeepOut vs ((IsTrack Or IsArc) And Not InPoly) And IsFree and IsKeepOut] p1: gap=0 ignorepadtopadclearanceinfootprint=FALSE
Clearance Clearance_Poly [InPolygon] p2: gap=8 ignorepadtopadclearanceinfootprint=TRUE
Clearance Clearance_FiducialMark [IsKeepOut and InComponentClass('FiducialMark') vs IsPad and InComponentClass('FiducialMark')] p3: gap=0 ignorepadtopadclearanceinfootprint=FALSE
Clearance [All] p4: gap=6 ignorepadtopadclearanceinfootprint=TRUE
ComponentClearance ComponentClearance_MountingHoles_FiducialMarks [InComponentClass('Mounting Holes') vs InComponentClass('FiducialMark')] p1: gap=50 collisioncheckmode=3 verticalgap=10 showdistances=FALSE
ComponentClearance ComponentClearance_Shunt [InComponentClass('Header') vs InComponentClass('Shunt')] p2: gap=0 collisioncheckmode=3 verticalgap=0 showdistances=FALSE
ComponentClearance ComponentClearance_Logo [InComponentClass('Logo')] p3: gap=30 collisioncheckmode=3 verticalgap=10 showdistances=FALSE
ComponentClearance ComponentClearance_ScrewToNut [(HasFootprint('NY PMS 440 0025 PH')) vs (HasFootprint('Keystone_1902C'))] p4: gap=5 collisioncheckmode=3 verticalgap=10 showdistances=FALSE
ComponentClearance ComponentClearance_MountingHoles [InComponentClass('Mounting Holes')] p5: gap=100 collisioncheckmode=3 verticalgap=100000 showdistances=FALSE
ComponentClearance ComponentClearance_SmallPassives [HasFootprint('0201*') or HasFootprint('0402*') or HasFootprint('0508') or HasFootprint('0603*') or HasFootprint('0612') or HasFootprint('0805*') or HasFootprint('0815*') or HasFootprint('0830*') or HasFootprint('1206*') or HasFootprint('1210*') or HasFootprint('1808*') or HasFootprint('1812*') or HasFootprint('1825*') or HasFootprint('2010*') or HasFootprint('2220*') or HasFootprint('2225*') or HasFootprint('2512*') or HasFootprint('2728*') or HasFootprint('3518*') vs HasFootprint('0201*') or HasFootprint('0402*') or HasFootprint('0508') or HasFootprint('0603*') or HasFootprint('0612') or HasFootprint('0805*') or HasFootprint('0815*') or HasFootprint('0830*') or HasFootprint('1206*') or HasFootprint('1210*') or HasFootprint('1808*') or HasFootprint('1812*') or HasFootprint('1825*') or HasFootprint('2010*') or HasFootprint('2220*') or HasFootprint('2225*') or HasFootprint('2512*') or HasFootprint('2728*') or HasFootprint('3518*')] p6: gap=14.96 collisioncheckmode=3 verticalgap=10 showdistances=FALSE
ComponentClearance ComponentClearance_THtoSMT [IsThruComponent vs IsSMTComponent] p7: gap=30 collisioncheckmode=3 verticalgap=30 showdistances=FALSE
ComponentClearance ComponentClearance_THtoTH [IsThruComponent vs IsThruComponent] p8: gap=20 collisioncheckmode=3 verticalgap=30 showdistances=FALSE
ComponentClearance [All] p9: gap=20 collisioncheckmode=3 verticalgap=10 showdistances=FALSE
DiffPairsRouting [All] p1: maxlimit=100 minlimit=10 mostfreqgap=10 toplayer_minwidth=15 toplayer_maxwidth=15 toplayer_prefwidth=15 midlayer1_minwidth=15 midlayer1_maxwidth=15 midlayer1_prefwidth=15 midlayer2_minwidth=15 midlayer2_maxwidth=15 midlayer2_prefwidth=15 midlayer3_minwidth=15 midlayer3_maxwidth=15 midlayer3_prefwidth=15 midlayer4_minwidth=15 midlayer4_maxwidth=15 midlayer4_prefwidth=15 midlayer5_minwidth=15 midlayer5_maxwidth=15 midlayer5_prefwidth=15 midlayer6_minwidth=15 midlayer6_maxwidth=15 midlayer6_prefwidth=15 midlayer7_minwidth=15 midlayer7_maxwidth=15 midlayer7_prefwidth=15 midlayer8_minwidth=15 midlayer8_maxwidth=15 midlayer8_prefwidth=15 midlayer9_minwidth=15 midlayer9_maxwidth=15 midlayer9_prefwidth=15 midlayer10_minwidth=15 midlayer10_maxwidth=15 midlayer10_prefwidth=15 midlayer11_minwidth=15 midlayer11_maxwidth=15 midlayer11_prefwidth=15 midlayer12_minwidth=15 midlayer12_maxwidth=15 midlayer12_prefwidth=15 bottomlayer_minwidth=15 bottomlayer_maxwidth=15 bottomlayer_prefwidth=15 maxuncoupledlength=1000
FabricationTestPointUsage TestPointUsage [All] p1: valid=2 allowmultiple=FALSE
FabricationTestpoint Testpoint [All] p1: side=3 testpointundercomponent=TRUE minsize=40 maxsize=100 preferedsize=60 minholesize=0 maxholesize=40 preferedholesize=32 testpointgrid=1 allowsidetop=TRUE allowsidebottom=TRUE usegrid=TRUE gridtolerance=0.01
FanoutControl Fanout_LCC [IsLCC] p1: bgadir=Out bgaviamode=Centered fanoutstyle=Auto fanoutdirection=Alternating viagrid=1 // Fanout_LCC (Default Rule)
FanoutControl Fanout_BGA [IsBGA] p2: bgadir=Out bgaviamode=Centered fanoutstyle=Auto fanoutdirection=Alternating viagrid=1 // Fanout_BGA (Default Rule)
FanoutControl Fanout_Default [All] p4: bgadir=Out bgaviamode=Centered fanoutstyle=Auto fanoutdirection=Alternating viagrid=1 // Fanout_Default (Default Rule)
FanoutControl Fanout_Small [(CompPinCount < 5)] p5: bgadir=Out bgaviamode=Centered fanoutstyle=Auto fanoutdirection=OutThenIn viagrid=1 // Fanout_Small (Default Rule)
HoleSize [All] p1: absolutevalues=TRUE maxlimit=251 minlimit=7.87 maxpercent=80.000 minpercent=20.000
MinimumAnnularRing MinimumAnnularRing_ThermalPadVias [IsVia and InAnyComponent] p1: minimumring=5.91
MinimumAnnularRing [All] p2: minimumring=4
MinimumSolderMaskSliver MinimumSolderMaskSliver_Logo [InComponentClass('Logo') vs InComponentClass('Logo')] p1: minsoldermaskwidth=0.7
MinimumSolderMaskSliver [All] p2: minsoldermaskwidth=3.94
PlaneConnect [All] p1: planeconnectstyle=Relief reliefexpansion=10 reliefentries=4 reliefconductorwidth=10 reliefairgap=10
PolygonConnect [All] p1: connectstyle=Direct reliefconductorwidth=10 reliefentries=4 polygonreliefangle="90 Angle" airgapwidth=10
RoutingVias ThermalPadVias [IsVia and InAnyComponent] p1: holewidth=7.87 width=19.68 viastyle="Through Hole" minholewidth=7.87 minwidth=19.68 maxholewidth=12.99 maxwidth=23.62
RoutingVias [All] p2: holewidth=16 width=34 viastyle="Through Hole" minholewidth=7.87 minwidth=24 maxholewidth=40 maxwidth=65
SilkToBoardRegionClearance [Not ((IsComment or IsDesignator) And (Hide <> 'False')) and not InRegion(1000,500,4000,800)] p1:
SilkToSilkClearance SilkToSilkClearance_Pb-FreeLogo [(HasFootprint('Pb-Free_Overlay_Medium') OR HasFootprint('Pb-Free_Overlay_Small')) vs (HasFootprint('Pb-Free_Overlay_Medium') OR HasFootprint('Pb-Free_Overlay_Small'))] p1: silktosilkclearance=0
SilkToSilkClearance [All] p2: silktosilkclearance=3.94
SilkToSolderMaskClearance SilkToComponentPadClearance [(IsPad or IsFill or IsRegion) and InAnycomponent] p1: minsilkscreentomaskgap=5 clearancetoexposedcopper=TRUE
SilkToSolderMaskClearance "Silk to Solder Mask Opening" [All] p2: minsilkscreentomaskgap=3.94 clearancetoexposedcopper=FALSE
SolderMaskExpansion [All] p1: expansion=1.97 istentingtop=FALSE
UnRoutedNet [All] p1: checkbadconnections=TRUE
Width [All] p1: maxlimit=100 minlimit=6 preferedwidth=10
14 further rules are at their usual default settings.

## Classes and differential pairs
component class PMP23340E3_UCD_Control: C1U C2U C3U C4U C5U C6U C7U C8U C9U C10U C11U C12U C13U C14U C15U C16U C17U C18U C19U C20U C21U C22U C23U C24U C25U R1U R2U R3U R4U R5U R6U R7U R8U R9U R10U R11U R12U R13U R14U R15U R16U R17U R18U RT1U RT2U TP1U TP2U U1U U2U U3U
component class PMP23340E3_UCD_Power_Stage: C26U C27U C28U C29U C30U C31U C32U C33U C34U C35U C36U C37U C38U C39U C40U C41U C42U C43U C44U C45U C46U C47U C48U C49U C50U C51U C52U C53U C54U C55U C56U C57U C58U C59U C60U C61U C62U C63U C64U C65U C66U C67U C68U C69U C70U C71U C72U C73U C74U C75U C76U C77U C78U C79U C80U C81U C82U C83U C84U C85U C86U C87U C88U C89U C90U C91U C92U C93U C94U C95U C96U C97U C98U C99U C100U C101U C102U C103U C104U C105U C106U C107U C108U C109U C110U C111U C112U C113U C114U C115U C116U C117U C118U C119U C120U C121U C122U C123U C124U C125U C126U C127U C128U C129U C130U C131U C132U C133U C134U C135U Gnd1U Gnd2U Gnd3U Gnd4U Gnd5U Gnd6U J1 J1U L1U L2U L3U L4U NT1U Q1U Q2U Q3U Q4U Q5U Q6U Q7U Q8U R19U R20U R21U R22U R23U R24U R25U R26U R27U R28U R29U R30U R31U R32U R33U R34U R35U R36U R37U R38U R39U R40U R41U R42U R43U R44U R45U R46U TP3U TP4U TP5U TP6U TP7U TP8U TP9U TP10U TP11U TP12U TP13U TP14U TP15U U4U U5U U6U U7U U8U U9U Vin1U Vout1U Vout2U Vout3U Vout4U Vout5U Vout6U
component class AssemblyNote: ZZ1U ZZ2U ZZ3U ZZ4U
component class PMP23340E3_UCD_Hardware: Logo1U Logo2U Logo3U Logo4U ZZ1U ZZ2U ZZ3U ZZ4U
component class Logo: Logo2U

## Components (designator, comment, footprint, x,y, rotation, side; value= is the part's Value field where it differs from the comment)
C1U "GRM033R60J225ME47D" 0201_040 52.21,507.88 r180 bottom value=2.2uF
C2U "ATC530Z104KT10T" 0201_033L 32.22,499.8 r90 top value=0.1uF
C3U "GRM033R60J225ME47D" 0201_040 155.38,652.5 r180 bottom value=2.2uF
C4U "GRM033R60J225ME47D" 0201_040 159.36,694.51 r180 top value=2.2uF
C5U "GRM033R60J225ME47D" 0201_040 154.35,622.39 r180 bottom value=2.2uF
C6U "ATC530Z104KT10T" 0201_033L 157.56,666.32 r0 top value=0.1uF
C7U "ATC530Z104KT10T" 0201_033L 149.75,684.73 r0 bottom value=0.1uF
C8U "GRM033R60J225ME47D" 0201_040 103.33,694.72 r0 top value=2.2uF
C9U "ATC530Z104KT10T" 0201_033L 113.14,665.84 r180 top value=0.1uF
C10U "GRM033R60J225ME47D" 0201_040 206.69,361.22 r90 top value=2.2uF
C11U "GJM0335C1E100JB01D" 0201 245.9,677.98 r90 top value=10pF
C12U "GJM0335C1E100JB01D" 0201 216.95,677.57 r90 top value=10pF
C13U "GRM0335C1H100JA01D" 0201_033 74.78,446.91 r0 bottom value=10pF
C14U "GRM033R71C222KA88D" 0201 121.17,357.15 r90 top value=2200pF
C15U "GRM033R71C222KA88D" 0201 85.84,358.28 r90 top value=2200pF
C16U "CGA1A2X7R1H221K030BA" 0201_033 283.46,296.37 r0 bottom value=220pF
C17U "ATC530Z104KT10T" 0201_033L 194.36,411.11 r90 bottom value=0.1uF
C18U "GRM033R71C102KA01D" 0201 57.89,666.63 r180 top value=1000pF
C19U "GRM033R71C102KA01D" 0201 178.15,360.24 r90 top value=1000pF
C20U "GRM033R71C102KA01D" 0201 56.42,359.88 r90 top value=1000pF
C21U "GRM033R71C102KA01D" 0201 75.09,418.19 r180 bottom value=1000pF
C22U "GRM033R71C102KA01D" 0201 149.91,360.34 r90 top value=1000pF
C23U "CGA1A2X7R1H221K030BA" 0201_033 294.14,481.45 r0 bottom value=220pF
C24U "GRM033R61A105ME15D" 0201 380,360.1 r180 top value=1uF
C25U "GRM033R61A105ME15D" 0201 285.71,300.03 r270 top value=1uF
C26U "C2012X5R2A475K125AC" FP-C2012X5R2A475K125AC_0805-MFG 298.23,957.68 r0 top value=4.7µF
C27U "C2012X5R2A475K125AC" FP-C2012X5R2A475K125AC_0805-MFG 308.58,1027.46 r0 top value=4.7µF
C28U "C2012X5R2A475K125AC" FP-C2012X5R2A475K125AC_0805-MFG 308.13,1097.43 r0 top value=4.7µF
C29U "C2012X5R2A475K125AC" FP-C2012X5R2A475K125AC_0805-MFG 308.07,769.68 r0 bottom value=4.7µF
C30U "C2012X5R2A475K125AC" FP-C2012X5R2A475K125AC_0805-MFG 416.61,669.46 r180 bottom value=4.7µF
C31U "C2012X5R2A475K125AC" FP-C2012X5R2A475K125AC_0805-MFG 418.31,741.14 r180 bottom value=4.7µF
C32U "C2012X5R2A475K125AC" FP-C2012X5R2A475K125AC_0805-MFG 417.87,810.48 r180 bottom value=4.7µF
C33U "C2012X5R2A475K125AC" FP-C2012X5R2A475K125AC_0805-MFG 415.39,917 r180 top value=4.7µF
C34U "C2012X5R2A475K125AC" FP-C2012X5R2A475K125AC_0805-MFG 414.9,986.57 r180 top value=4.7µF
C35U "C2012X5R2A475K125AC" FP-C2012X5R2A475K125AC_0805-MFG 308.11,839.19 r0 bottom value=4.7µF
C36U "C2012X5R2A475K125AC" FP-C2012X5R2A475K125AC_0805-MFG 415.83,1055.96 r180 top value=4.7µF
C37U "C2012X5R2A475K125AC" FP-C2012X5R2A475K125AC_0805-MFG 308.07,699.8 r0 bottom value=4.7µF
C38U "GRM033R61A105ME15D" 0201 866.14,284.45 r180 bottom value=1uF
C39U "GRT21BR61E226ME13L" 0805_HV 1964.62,187.39 r0 bottom value=22uF
C40U "GRT21BR61E226ME13L" 0805_HV 1488.25,187.39 r180 bottom value=22uF
C41U "GRT21BR61E226ME13L" 0805_HV 1176.87,187.39 r0 bottom value=22uF
C42U "GRT21BR61E226ME13L" 0805_HV 708.49,187.39 r180 bottom value=22uF
C43U "GRM0335C1H100JA01D" 0201_033 1009.84,284.45 r180 bottom value=10pF
C44U "160R07X104KV4T" 0402_065 495.66,612.06 r180 top value=0.1uF
C45U "GRM0335C1H100JA01D" 0201_033 847.46,339.1 r90 top value=10pF
C46U "GRM0335C1H100JA01D" 0201_033 803.72,421.51 r180 bottom value=10pF
C47U "160R07X104KV4T" 0402_065 340.77,681.68 r270 top value=0.1uF
C48U "GRM0335C1H100JA01D" 0201_033 1067.91,422.24 r180 top value=10pF
C49U "GRM0335C1H100JA01D" 0201_033 1084.88,271.7 r0 bottom value=10pF
C50U "GRM155C81C225ME15D" FP-GRM155C81C225ME15D_0402-MFG 2081.83,464.29 r90 bottom value=2.2µF
C51U "GRM155C81C225ME15D" FP-GRM155C81C225ME15D_0402-MFG 2041.77,464.29 r90 bottom value=2.2µF
C52U "GRM155C81C225ME15D" FP-GRM155C81C225ME15D_0402-MFG 2001.71,464.29 r90 bottom value=2.2µF
C53U "GRM155C81C225ME15D" FP-GRM155C81C225ME15D_0402-MFG 1961.65,464.29 r90 bottom value=2.2µF
C54U "GRM155C81C225ME15D" FP-GRM155C81C225ME15D_0402-MFG 1921.59,464.29 r90 bottom value=2.2µF
C55U "GRM155C81C225ME15D" FP-GRM155C81C225ME15D_0402-MFG 1881.54,464.29 r90 bottom value=2.2µF
C56U "GRM155C81C225ME15D" FP-GRM155C81C225ME15D_0402-MFG 1561.98,464.1 r90 bottom value=2.2µF
C57U "GRM155C81C225ME15D" FP-GRM155C81C225ME15D_0402-MFG 1521.4,464.1 r90 bottom value=2.2µF
C58U "GRM155C81C225ME15D" FP-GRM155C81C225ME15D_0402-MFG 1480.81,464.1 r90 bottom value=2.2µF
C59U "GRM155C81C225ME15D" FP-GRM155C81C225ME15D_0402-MFG 1440.23,464.1 r90 bottom value=2.2µF
C60U "GRM155C81C225ME15D" FP-GRM155C81C225ME15D_0402-MFG 1399.64,464.1 r90 bottom value=2.2µF
C61U "GRM155C81C225ME15D" FP-GRM155C81C225ME15D_0402-MFG 1359.06,464.1 r90 bottom value=2.2µF
C62U "GRM155C81C225ME15D" FP-GRM155C81C225ME15D_0402-MFG 1398.7,463.73 r90 top value=2.2µF
C63U "GRM155C81C225ME15D" FP-GRM155C81C225ME15D_0402-MFG 1439.05,463.73 r90 top value=2.2µF
C64U "GRM155C81C225ME15D" FP-GRM155C81C225ME15D_0402-MFG 1479.41,463.73 r90 top value=2.2µF
C65U "GRM155C81C225ME15D" FP-GRM155C81C225ME15D_0402-MFG 1519.76,463.73 r90 top value=2.2µF
C66U "GRM155C81C225ME15D" FP-GRM155C81C225ME15D_0402-MFG 1560.12,463.73 r90 top value=2.2µF
C67U "GRM155C81C225ME15D" FP-GRM155C81C225ME15D_0402-MFG 1600.47,463.73 r90 top value=2.2µF
C68U "GRM155C81C225ME15D" FP-GRM155C81C225ME15D_0402-MFG 1893,465.11 r90 top value=2.2µF
C69U "GRM155C81C225ME15D" FP-GRM155C81C225ME15D_0402-MFG 1933.15,465.11 r90 top value=2.2µF
C70U "GRM155C81C225ME15D" FP-GRM155C81C225ME15D_0402-MFG 1973.31,465.11 r90 top value=2.2µF
C71U "GRM155C81C225ME15D" FP-GRM155C81C225ME15D_0402-MFG 2013.47,465.11 r90 top value=2.2µF
C72U "GRM155C81C225ME15D" FP-GRM155C81C225ME15D_0402-MFG 2053.63,465.11 r90 top value=2.2µF
C73U "GRM155C81C225ME15D" FP-GRM155C81C225ME15D_0402-MFG 2093.78,465.11 r90 top value=2.2µF
C74U "GRM033R61A105ME15D" 0201 1008.35,284.07 r0 top value=1uF
C75U "GRM155R62A104KE14D" 0402 325.71,903 r180 bottom value=0.1uF
C76U "GRM155R62A104KE14D" 0402 325.71,944.47 r180 bottom value=0.1uF
C77U "GRM155R62A104KE14D" 0402 322.83,986.22 r180 bottom value=0.1uF
C78U "GRM155R62A104KE14D" 0402 331.19,901.24 r180 top value=0.1uF
C79U "GRM155R62A104KE14D" 0402 331.19,854.89 r180 top value=0.1uF
C80U "GRM155R62A104KE14D" 0402 331.19,808.54 r180 top value=0.1uF
C81U "C1206C224K3JAC7800" FP-C1206C224K3JAC7800_1206-MFG 2197.6,500.99 r180 bottom value=220nF
C82U "GRM0335C1H100JA01D" 0201_033 856.91,284.07 r0 top value=10pF
C83U "C1206C224K3JAC7800" FP-C1206C224K3JAC7800_1206-MFG 2192.68,501.56 r180 top value=220nF
C84U "C1206C224K3JAC7800" FP-C1206C224K3JAC7800_1206-MFG 2192.68,840.51 r180 top value=220nF
C85U "GRM033R61A105ME15D" 0201 1651.82,281.49 r180 bottom value=1uF
C86U "C1206C224K3JAC7800" FP-C1206C224K3JAC7800_1206-MFG 2192.68,755.5 r180 top value=220nF
C87U "C1206C224K3JAC7800" FP-C1206C224K3JAC7800_1206-MFG 2192.68,672.14 r180 top value=220nF
C88U "GRM0335C1H100JA01D" 0201_033 1810.36,285.63 r180 bottom value=10pF
C89U "C1206C224K3JAC7800" FP-C1206C224K3JAC7800_1206-MFG 2192.68,586.83 r180 top value=220nF
C90U "GRM0335C1H100JA01D" 0201_033 1632.87,336.61 r90 top value=10pF
C91U "GRM0335C1H100JA01D" 0201_033 1600.87,422.04 r180 bottom value=10pF
C92U "C1206C224K3JAC7800" FP-C1206C224K3JAC7800_1206-MFG 2192.68,1093.47 r180 top value=220nF
C93U "C1206C224K3JAC7800" FP-C1206C224K3JAC7800_1206-MFG 2192.68,1009.65 r180 top value=220nF
C94U "160R07X104KV4T" 0402_065 492.13,1120.08 r180 bottom value=0.1uF
C95U "GRM0335C1H100JA01D" 0201_033 1859.25,423.23 r180 top value=10pF
C96U "GRM0335C1H100JA01D" 0201_033 1887.59,269.57 r0 bottom value=10pF
C97U "C1206C224K3JAC7800" FP-C1206C224K3JAC7800_1206-MFG 2192.68,924.47 r180 top value=220nF
C98U "160R07X104KV4T" 0402_065 340.55,1072.83 r90 bottom value=0.1uF
C99U "GRM155C81C225ME15D" FP-GRM155C81C225ME15D_0402-MFG 1294.45,464.29 r90 bottom value=2.2µF
C100U "GRM155C81C225ME15D" FP-GRM155C81C225ME15D_0402-MFG 1254.47,464.29 r90 bottom value=2.2µF
C101U "GRM155C81C225ME15D" FP-GRM155C81C225ME15D_0402-MFG 1214.48,464.29 r90 bottom value=2.2µF
C102U "GRM155C81C225ME15D" FP-GRM155C81C225ME15D_0402-MFG 1174.5,464.29 r90 bottom value=2.2µF
C103U "GRM155C81C225ME15D" FP-GRM155C81C225ME15D_0402-MFG 1134.52,464.29 r90 bottom value=2.2µF
C104U "GRM155C81C225ME15D" FP-GRM155C81C225ME15D_0402-MFG 1094.54,464.29 r90 bottom value=2.2µF
C105U "GRM155C81C225ME15D" FP-GRM155C81C225ME15D_0402-MFG 762.29,464.29 r90 bottom value=2.2µF
C106U "GRM155C81C225ME15D" FP-GRM155C81C225ME15D_0402-MFG 722.34,464.29 r90 bottom value=2.2µF
C107U "GRM155C81C225ME15D" FP-GRM155C81C225ME15D_0402-MFG 682.4,464.29 r90 bottom value=2.2µF
C108U "GRM155C81C225ME15D" FP-GRM155C81C225ME15D_0402-MFG 642.45,464.29 r90 bottom value=2.2µF
C109U "GRM155C81C225ME15D" FP-GRM155C81C225ME15D_0402-MFG 602.51,464.29 r90 bottom value=2.2µF
C110U "GRM155C81C225ME15D" FP-GRM155C81C225ME15D_0402-MFG 562.56,464.29 r90 bottom value=2.2µF
C111U "C1206C224K3JAC7800" FP-C1206C224K3JAC7800_1206-MFG 2197.6,585.04 r180 bottom value=220nF
C112U "C1206C224K3JAC7800" FP-C1206C224K3JAC7800_1206-MFG 2197.6,670.35 r180 bottom value=220nF
C113U "C1206C224K3JAC7800" FP-C1206C224K3JAC7800_1206-MFG 2197.6,753.71 r180 bottom value=220nF
C114U "GRM155C81C225ME15D" FP-GRM155C81C225ME15D_0402-MFG 582.82,464.74 r90 top value=2.2µF
C115U "GRM155C81C225ME15D" FP-GRM155C81C225ME15D_0402-MFG 623.11,464.74 r90 top value=2.2µF
C116U "GRM155C81C225ME15D" FP-GRM155C81C225ME15D_0402-MFG 663.39,464.74 r90 top value=2.2µF
C117U "GRM155C81C225ME15D" FP-GRM155C81C225ME15D_0402-MFG 703.68,464.74 r90 top value=2.2µF
C118U "GRM155C81C225ME15D" FP-GRM155C81C225ME15D_0402-MFG 743.97,464.74 r90 top value=2.2µF
C119U "GRM155C81C225ME15D" FP-GRM155C81C225ME15D_0402-MFG 784.26,464.74 r90 top value=2.2µF
C120U "GRM155C81C225ME15D" FP-GRM155C81C225ME15D_0402-MFG 1102.36,464.16 r90 top value=2.2µF
C121U "GRM155C81C225ME15D" FP-GRM155C81C225ME15D_0402-MFG 1142.52,464.16 r90 top value=2.2µF
C122U "GRM155C81C225ME15D" FP-GRM155C81C225ME15D_0402-MFG 1182.67,464.16 r90 top value=2.2µF
C123U "GRM155C81C225ME15D" FP-GRM155C81C225ME15D_0402-MFG 1222.83,464.16 r90 top value=2.2µF
C124U "GRM155C81C225ME15D" FP-GRM155C81C225ME15D_0402-MFG 1262.99,464.16 r90 top value=2.2µF
C125U "GRM155C81C225ME15D" FP-GRM155C81C225ME15D_0402-MFG 1303.15,464.16 r90 top value=2.2µF
C126U "C1206C224K3JAC7800" FP-C1206C224K3JAC7800_1206-MFG 2197.6,929.47 r180 bottom value=220nF
C127U "C1206C224K3JAC7800" FP-C1206C224K3JAC7800_1206-MFG 2197.6,1013.43 r180 bottom value=220nF
C128U "GRM033R61A105ME15D" 0201 1810.79,283.29 r0 top value=1uF
C129U "C1206C224K3JAC7800" FP-C1206C224K3JAC7800_1206-MFG 2197.6,1097.25 r180 bottom value=220nF
C130U "C1206C224K3JAC7800" FP-C1206C224K3JAC7800_1206-MFG 2197.6,845.87 r180 bottom value=220nF
C131U "GRT21BR61E226ME13L" 0805_HV 1183.09,187.39 r0 top value=22uF
C132U "GRT21BR61E226ME13L" 0805_HV 718.95,187.39 r180 top value=22uF
C133U "GRT21BR61E226ME13L" 0805_HV 1495.72,187.39 r180 top value=22uF
C134U "GRT21BR61E226ME13L" 0805_HV 1959.87,187.39 r0 top value=22uF
C135U "GRM0335C1H100JA01D" 0201_033 1642.33,285.6 r0 top value=10pF
Gnd1U "3621-0-32-15-00-00-08-0" Mill-Max_3621-0-32-xx-00-00-08-0 482.16,-32.19 r0 top
Gnd2U "3621-0-32-15-00-00-08-0" Mill-Max_3621-0-32-xx-00-00-08-0 1417.4,-32.19 r0 top
Gnd3U "3621-0-32-15-00-00-08-0" Mill-Max_3621-0-32-xx-00-00-08-0 2040.89,-32.19 r0 top
Gnd4U "3621-0-32-15-00-00-08-0" Mill-Max_3621-0-32-xx-00-00-08-0 638.03,-32.19 r0 top
Gnd5U "3621-0-32-15-00-00-08-0" Mill-Max_3621-0-32-xx-00-00-08-0 1261.53,-32.19 r0 top
Gnd6U "3621-0-32-15-00-00-08-0" Mill-Max_3621-0-32-xx-00-00-08-0 2196.77,-32.19 r0 top
J1U "ASP-231707-01" FP-FTSH-104-04-L-D-RA_HDR8-MFG 121.2,60.86 r0 top
L1U "BLM03AX241SN1D" 0201_033 904.71,276.99 r90 bottom
L2U "BLM03AX241SN1D" 0201_033 970.05,278.02 r90 top
L3U "BLM03AX241SN1D" 0201_033 1691.8,270.46 r90 bottom
L4U "BLM03AX241SN1D" 0201_033 1765.81,271.77 r90 top
Logo1U "CE Mark" CE_Mark_5mm 653.3,700.83 r90 bottom
Logo2U "Texas Instruments" TI_Symbol_Overlay_Small 706.67,1050.19 r0 top
Logo3U "FCC disclaimer" FCC_disclaimer 777.73,3884.85 r0 top
Logo4U "WEEE logo" WEEE_Minimum 1991.82,812.47 r180 bottom
NT1U "Net-Tie" NetTie_0402 398.08,214.02 r180 top net-tie
Q1U "EPC2066" D0650#1 701.37,348.25 r180 top
Q2U "EPC2066" D0650#2 701.37,348.25 r180 bottom
Q3U "EPC2066" D0650#1 1180.13,349.64 r0 top
Q4U "EPC2066" D0650#2 1180.22,349.96 r0 bottom
Q5U "EPC2066" D0650#1 1482.8,349.96 r180 top
Q6U "EPC2066" D0650#2 1482.8,349.96 r180 bottom
Q7U "EPC2066" D0650#1 1987.25,351.07 r0 top
Q8U "EPC2066" D0650#2 1987.25,351.07 r0 bottom
R1U "RC0201FR-071RL" 0201 68.35,552.47 r90 bottom value=1.00
R2U "RC0201JR-7D2K2L" 0201 201.37,295.08 r180 top value=2.2k
R3U "RC0201FR-07845RL" 0201 97.64,258.91 r0 bottom value=845
R4U "RC0201FR-07845RL" 0201 97.64,287.88 r0 bottom value=845
R5U "RC0201FS-7D1KL" 0201 283.46,267.72 r0 bottom value=1.00k
R6U "RC0201JR-7D10KL" 0201 57.22,727.74 r0 top value=10k
R7U "RC0201FS-7D10KL" 0201 131.88,312.62 r0 top value=10.0k
R8U "CRCW0402150KFKED" 0402 59.55,278.81 r0 top value=150k
R9U "RC0201JS-7D10KL" 0201 271.44,764.83 r180 top value=10k
R10U "RC0201JS-7D10KL" 0201 380,388.64 r180 top value=10k
R11U "RC0402FR-0714KL" 0402 384.88,271.92 r90 bottom value=14.0k
R12U "RC0201FS-7D24R3L" 0201 243.32,296.37 r180 bottom value=24.3
R13U "RC0402FR-0714KL" 0402 423.94,274.15 r90 bottom value=14.0k
R14U "RC0201DR-071KL" 0201 56.63,695.23 r180 top value=1.00k
R15U "RC0201DR-071KL" 0201 90.92,312.39 r0 top value=1.00k
R16U "RC0201DR-074K7L" 0201 49.82,312.62 r180 top value=4.70k
R17U "RC0201FS-7D1KL" 0201 292.41,509.5 r0 bottom value=1.00k
R18U "RC0201FR-075K11L" 0201 243,267.88 r180 bottom value=5.11k
R19U "CRCW020120R0FNED" 0201_033 971.46,278.54 r90 bottom value=20.0
R20U "RC0201FS-7D10RL" 0201 848.29,371.7 r90 bottom value=10.0
R21U "RC0201DR-075K11L" 0201 848.29,330.36 r90 bottom value=5.11k
R22U "RC0201JR-070RL" "FP-RC0201JR-070RL_0201 (0603 Metric)-IPC_C" 937.99,278.54 r90 bottom
R23U "RC0201JR-070RL" "FP-RC0201JR-070RL_0201 (0603 Metric)-IPC_C" 1045.12,448.71 r180 bottom
R24U "RC0201FS-7D2RL" 0201 847.46,379.3 r90 top value=2.00
R25U "RC0201FS-7D2RL" 0201 847.6,424.29 r90 bottom value=2.00
R26U "RC0201FS-7D2RL" 0201 1033.45,411.01 r270 top value=2.00
R27U "RC0201FS-7D2RL" 0201 1034.45,395.67 r270 bottom value=2.00
R28U "CRCW020120R0FNED" 0201_033 900.59,277.56 r90 top value=20.0
R29U "RC0201FS-7D10RL" 0201 1032.41,353.55 r90 top value=10.0
R30U "RC0201DR-075K11L" 0201 1086.78,275.04 r180 top value=5.11k
R31U "RC0201JR-070RL" "FP-RC0201JR-070RL_0201 (0603 Metric)-IPC_C" 937.26,276.83 r90 top
R32U "RC0201JR-070RL" "FP-RC0201JR-070RL_0201 (0603 Metric)-IPC_C" 828.15,445.56 r0 top
R33U "CRCW020120R0FNED" 0201_033 1769,273.22 r90 bottom value=20.0
R34U "RC0201FS-7D10RL" 0201 1639.2,374.45 r90 bottom value=10.0
R35U "RC0201DR-075K11L" 0201 1639.2,334.1 r90 bottom value=5.11k
R36U "RC0201JR-070RL" "FP-RC0201JR-070RL_0201 (0603 Metric)-IPC_C" 1730.4,269.09 r90 bottom
R37U "RC0201FS-7D2RL" 0201 1632.87,376.97 r90 top value=2.00
R38U "RC0201FS-7D2RL" 0201 1639.2,426.62 r90 bottom value=2.00
R39U "RC0201JR-070RL" "FP-RC0201JR-070RL_0201 (0603 Metric)-IPC_C" 1833.84,447.29 r180 bottom
R40U "RC0201FS-7D2RL" 0201 1824.36,411.01 r270 top value=2.00
R41U "RC0201FS-7D2RL" 0201 1823.34,396.3 r270 bottom value=2.00
R42U "CRCW020120R0FNED" 0201_033 1693.21,277.12 r90 top value=20.0
R43U "RC0201FS-7D10RL" 0201 1823.11,353.55 r90 top value=10.0
R44U "RC0201DR-075K11L" 0201 1887.66,273.99 r180 top value=5.11k
R45U "RC0201JR-070RL" "FP-RC0201JR-070RL_0201 (0603 Metric)-IPC_C" 1727.45,271.65 r90 top
R46U "RC0201JR-070RL" "FP-RC0201JR-070RL_0201 (0603 Metric)-IPC_C" 1642.2,457.87 r0 top
RT1U "TMP6131DECT" DEC0002A 333.68,753.89 r270 top
RT2U "TMP6131DECT" DEC0002A 525.89,342.39 r270 top
TP1U "TESTPOINT" TP_25MIL-SMT 449.91,491.04 r90 top
TP2U "TESTPOINT" TP_25MIL-SMT 448.82,558.93 r90 top
TP3U "TESTPOINT" TP_25MIL-SMT 2093.86,798.81 r90 top
TP4U "TESTPOINT" TP_25MIL-SMT 930.79,520.92 r0 top
TP5U "TESTPOINT" TP_25MIL-SMT 2157,386.05 r90 top
TP6U "TESTPOINT" TP_25MIL-SMT 1332.57,280 r90 top
TP7U "TESTPOINT" TP_25MIL-SMT 1331.4,411.23 r90 top
TP8U "TESTPOINT" TP_25MIL-SMT 549.73,285.86 r90 top
TP9U "TESTPOINT" TP_25MIL-SMT 1743.76,522.51 r90 top
TP10U "TESTPOINT" TP_25MIL-SMT 2005.61,253.7 r90 top
TP11U "TESTPOINT" TP_25MIL-SMT 669.76,253.7 r90 top
TP12U "TESTPOINT" TP_25MIL-SMT 1181.77,253.7 r90 top
TP13U "TESTPOINT" TP_25MIL-SMT 1450.48,253.7 r90 top
TP14U "TESTPOINT" TP_25MIL-SMT 585.95,923.89 r90 top
TP15U "TESTPOINT" TP_25MIL-SMT 584.4,814.14 r90 top
U1U "UCD3138ARJAT" RJA0040A-MFG 177.17,518.7 r90 top
U2U "TLV365DBVR" DBV0005A-MFG 280.51,386.81 r270 bottom
U3U "TLV75533PDRVR" DRV0006A 354.9,291.31 r0 top
U4U "UCD7138DRS" DRS0006A#1 937.3,373.03 r90 bottom
U5U "LMG2100R044" RAR0016A-MFG 462.64,757.18 r180 top
U6U "UCD7138DRS" DRS0006A#2 937.01,373.03 r90 top
U7U "UCD7138DRS" DRS0006A#1 1727.87,373.66 r90 bottom
U8U "LMG2100R044" RAR0016A-MFG 461.61,977.36 r180 bottom
U9U "UCD7138DRS" DRS0006A#2 1727.87,373.66 r90 top
Vin1U "3621-0-32-15-00-00-08-0" Mill-Max_3621-0-32-xx-00-00-08-0 326.29,-32.19 r0 top
Vout1U "3621-0-32-15-00-00-08-0" Mill-Max_3621-0-32-xx-00-00-08-0 1885.02,-32.19 r0 top
Vout2U "3621-0-32-15-00-00-08-0" Mill-Max_3621-0-32-xx-00-00-08-0 1573.27,-32.19 r0 top
Vout3U "3621-0-32-15-00-00-08-0" Mill-Max_3621-0-32-xx-00-00-08-0 1105.65,-32.19 r0 top
Vout4U "3621-0-32-15-00-00-08-0" Mill-Max_3621-0-32-xx-00-00-08-0 793.91,-32.19 r0 top
Vout5U "3621-0-32-15-00-00-08-0" Mill-Max_3621-0-32-xx-00-00-08-0 949.78,-32.19 r0 top
Vout6U "3621-0-32-15-00-00-08-0" Mill-Max_3621-0-32-xx-00-00-08-0 1729.15,-32.19 r0 top
ZZ1U "This Assembly Note is for PCB labels only" AssemblyNoteLabel 185,3938 r0 top
ZZ2U "These assemblies are ESD sensitive, ESD precautions shall be observed." AssemblyNote 185,3829.11 r0 top
ZZ3U "These assemblies must be clean and free from flux and all contaminants. Use of no clean flux is not acceptable." AssemblyNote 185,3740.56 r0 top
ZZ4U "These assemblies must comply with workmanship standards IPC-A-610 Class 2, unless otherwise specified." AssemblyNote 185,3652 r0 top

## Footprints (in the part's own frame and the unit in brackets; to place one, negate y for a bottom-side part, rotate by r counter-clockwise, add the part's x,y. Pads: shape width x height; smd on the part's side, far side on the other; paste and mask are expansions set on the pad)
0201 [mm] "Data from Kemet datasheet CC101_COM dated 7/28/11"
  rect 0.46x0.42 smd mask+0.048: 1(-0.33,0) 2(0.33,0)
  body extent -0.31,-0.16 0.31,0.16, height 0.26
0201_033 [mm] "SMD, 2-Leads, Height 0.33mm"
  rect 0.46x0.42 smd mask+0.048: 1(-0.33,0) 2(0.33,0)
  body extent -0.31,-0.16 0.31,0.16, height 0.33
0201_033L [mm] "0201"
  rect 0.36x0.32 smd mask+0.048: 1(-0.28,0) 2(0.28,0)
  body extent -0.31,-0.16 0.31,0.16, height 0.33
0201_040 [mm] "SMD, 2-Leads, Height 0.33mm"
  rect 0.46x0.42 smd mask+0.048: 1(-0.33,0) 2(0.33,0)
  body extent -0.31,-0.16 0.31,0.16, height 0.4
0402 [mm] "0402 from SM-752 data"
  rect 0.8x0.6 smd: 1(-0.6,0) 2(0.6,0)
  silkscreen extent -1.22,-0.52 1.22,0.52, body extent -0.55,-0.3 0.55,0.3, height 0.6
0402_065 [mm] "0402"
  rect 0.8x0.6 smd: 1(-0.6,0) 2(0.6,0)
  silkscreen extent -1.22,-0.52 1.22,0.52, body extent -0.55,-0.3 0.55,0.3, height 0.65
0805_HV [mil] "0805 with 30mil clearance between pads"
  rect 50x63 smd: 1(-40,0) 2(40,0)
  silkscreen extent -74,-40 74,40, body extent -43,-29 43,29, height 57
AssemblyNote [mil] "Assembly Note"
AssemblyNoteLabel [mil] "Assembly Note for PCB Labels"
CE_Mark_5mm [mil] "Minimum text height for CE Mark"
  silkscreen extent -138,-98 138,98
D0650#1 [mm]
  rrect50% 0.27x0.794 smd paste-0.037 mask-0.274: 1(-2.8,0.665) 2(-2.8,-0.665) 3(-2.4,0.665) 4(-2.4,-0.665) 5(-2,0.665) 7(-1.6,0.665) 8(-1.6,-0.665) 10(-1.2,-0.665) 11(-0.8,0.665) 12(-0.8,-0.665) 13(-0.4,0.665) 14(-0.4,-0.665) 15(0,0.665) 16(0,-0.665) 17(0.4,0.665) 18(0.4,-0.665) 19(0.8,0.665) 20(0.8,-0.665) 21(1.2,0.665) 22(1.2,-0.665) 23(1.6,0.665) 24(1.6,-0.665) 25(2,0.665) 26(2,-0.665) 27(2.4,0.665) 28(2.4,-0.665) 29(2.8,0.665) 30(2.8,-0.665)
  rrect50% 0.27x0.794 smd paste-0.037 mask-0.24: 6(-2,-0.665)
  rrect50% 0.27x0.795 smd paste-0.037 mask-0.274: 9(-1.2,0.665)
  oval 0.18x0.7 on Top Solder paste-0.18 mask+0: ""(-2.8,0.665) ""(-2.8,-0.665) ""(-2.4,0.665) ""(-2.4,-0.665) ""(-2,0.665) ""(-2,-0.665) ""(-1.6,0.665) ""(-1.6,-0.665) ""(-1.2,0.665) ""(-1.2,-0.665) ""(-0.8,0.665) ""(-0.8,-0.665) ""(-0.4,0.665) ""(-0.4,-0.665) ""(0,0.665) ""(0,-0.665) ""(0.4,0.665) ""(0.4,-0.665) ""(0.8,0.665) ""(0.8,-0.665) ""(1.2,0.665) ""(1.2,-0.665) ""(1.6,0.665) ""(1.6,-0.665) ""(2,0.665) ""(2,-0.665) ""(2.4,0.665) ""(2.4,-0.665) ""(2.8,0.665) ""(2.8,-0.665)
  silkscreen extent -3.13,-1.25 3.13,1.31, body extent -3.02,-1.15 3.03,1.16, height 0.79
D0650#2 [mm]
  rrect50% 0.27x0.794 smd paste-0.037 mask-0.274: 1(-2.8,0.665) 2(-2.8,-0.665) 3(-2.4,0.665) 4(-2.4,-0.665) 5(-2,0.665) 7(-1.6,0.665) 8(-1.6,-0.665) 10(-1.2,-0.665) 11(-0.8,0.665) 12(-0.8,-0.665) 13(-0.4,0.665) 14(-0.4,-0.665) 15(0,0.665) 16(0,-0.665) 17(0.4,0.665) 18(0.4,-0.665) 19(0.8,0.665) 20(0.8,-0.665) 21(1.2,0.665) 22(1.2,-0.665) 23(1.6,0.665) 24(1.6,-0.665) 25(2,0.665) 26(2,-0.665) 27(2.4,0.665) 28(2.4,-0.665) 29(2.8,0.665) 30(2.8,-0.665)
  rrect50% 0.27x0.794 smd paste-0.037 mask-0.24: 6(-2,-0.665)
  rrect50% 0.27x0.795 smd paste-0.037 mask-0.274: 9(-1.2,0.665)
  oval 0.18x0.7 on Bottom Solder paste-0.18 mask+0: ""(-2.8,0.665) ""(-2.8,-0.665) ""(-2.4,0.665) ""(-2.4,-0.665) ""(-2,0.665) ""(-2,-0.665) ""(-1.6,0.665) ""(-1.6,-0.665) ""(-1.2,0.665) ""(-1.2,-0.665) ""(-0.8,0.665) ""(-0.8,-0.665) ""(-0.4,0.665) ""(-0.4,-0.665) ""(0,0.665) ""(0,-0.665) ""(0.4,0.665) ""(0.4,-0.665) ""(0.8,0.665) ""(0.8,-0.665) ""(1.2,0.665) ""(1.2,-0.665) ""(1.6,0.665) ""(1.6,-0.665) ""(2,0.665) ""(2,-0.665) ""(2.4,0.665) ""(2.4,-0.665) ""(2.8,0.665) ""(2.8,-0.665)
  silkscreen extent -3.13,-1.25 3.13,1.31, body extent -3.02,-1.15 3.03,1.16, height 0.79
DBV0005A-MFG [mm]
  rrect17% 1.1x0.6 smd paste+0 mask+0: 1(-1.3,0.95) 2(-1.3,0) 3(-1.3,-0.95) 4(1.3,-0.95) 5(1.3,0.95)
  silkscreen extent -2.52,-1.53 0.87,1.53, body extent -1.4,-1.45 1.4,1.45, height 1.45
DEC0002A [mm] "X1SON-2"
  rrect57% 0.35x0.6 smd paste-0.5 mask-0.05: 1(-0.325,0) 2(0.325,0)
  rrect33% 0.3x0.5 on Top Paste: 1S(-0.35,0) 2S(0.35,0)
  body extent -0.5,-0.3 0.5,0.3, height 0.5
DRS0006A#1 [mm] "SON, 6-Leads, Body 3x3mm, Pitch 0.95mm, Thermal Pad 2x1.3mm, TI Recommended"
  rrect100% 0.7x0.35 smd: 1(-1.35,0.95) 2(-1.35,0) 3(-1.35,-0.95) 4(1.35,-0.95) 5(1.35,0) 6(1.35,0.95)
  rrect9% 1.126x1.71 on Bottom Paste: 7(0,0)
  rrect8% 1.2x1.9 smd paste-0.6: 7(0,0)
  silkscreen extent -1.73,-1.73 1.72,1.73, body extent -1.58,-1.57 1.57,1.58, height 0.81
DRS0006A#2 [mm] "SON, 6-Leads, Body 3x3mm, Pitch 0.95mm, Thermal Pad 2x1.3mm, TI Recommended"
  rrect100% 0.7x0.35 smd: 1(-1.35,0.95) 2(-1.35,0) 3(-1.35,-0.95) 4(1.35,-0.95) 5(1.35,0) 6(1.35,0.95)
  rrect9% 1.126x1.71 on Top Paste: 7(0,0)
  rrect8% 1.2x1.9 smd paste-0.6: 7(0,0)
  silkscreen extent -1.73,-1.73 1.72,1.73, body extent -1.58,-1.57 1.57,1.58, height 0.81
DRV0006A [mm] "SON, 6-Leads, Body 2x2mm, Pitch 0.65mm, Thermal Pad 1.6x1mm, TI Recommended"
  rrect33% 0.45x0.3 smd: 1(-0.975,0.65) 2(-0.975,0) 3(-0.975,-0.65) 4(0.975,-0.65) 5(0.975,0) 6(0.975,0.65)
  rrect14% 1x0.7 on Top Paste: 7(0,-0.45) 7(0,0.45)
  rrect10% 1x1.6 smd paste-0.5: 7(0,0)
  silkscreen extent -1.05,-1.2 1.05,1.2, body extent -1.05,-1.05 1.05,1.05, height 0.81
FCC_disclaimer [mil]
FP-C1206C224K3JAC7800_1206-MFG [mm]
  rrect11% 0.95x1.7 smd paste+0 mask+0: 1(-1.4,0) 2(1.4,0)
  silkscreen extent -0.55,-0.9 0.55,0.9, body extent -1.6,-0.8 1.6,0.8, height 1.8
FP-C2012X5R2A475K125AC_0805-MFG [mm]
  rrect13% 0.8x1.05 smd paste+0 mask+0: 1(-0.925,0) 2(0.925,0)
  silkscreen extent -0.15,-0.75 0.15,0.75, body extent -1.43,-0.85 1.43,0.85, height 0.25
FP-FTSH-104-04-L-D-RA_HDR8-MFG [mm]
  rrect9% 1.12x1.12 hole 0.71 paste-2539.97 mask+0: 1(-1.905,2.525)
  round 1.12 hole 0.71 paste-2539.97 mask+0: 2(-1.905,3.795) 3(-0.635,2.525) 4(-0.635,3.795) 5(0.635,2.525) 6(0.635,3.795) 7(1.905,2.525) 8(1.905,3.795)
  silkscreen extent -3.29,-1.32 2.57,2.65, body extent -2.5,-5.07 2.5,4, height 3.56
FP-GRM155C81C225ME15D_0402-MFG [mm]
  rrect22% 0.45x0.6 smd paste+0 mask+0: 1(-0.475,0) 2(0.475,0)
  silkscreen extent -0.61,-0.67 0.6,0.67, body extent -0.5,-0.25 0.5,0.25, height 0.55
"FP-RC0201JR-070RL_0201 (0603 Metric)-IPC_C" [mil]
  rrect38% 13.94x10.34 smd paste+0 mask+0: 1(-10.01,0) 2(10.01,0)
  body extent -12,-6 12,6, height 10
Mill-Max_3621-0-32-xx-00-00-08-0 [mm] "PCB Pin, 0.04\" DIA, R/A, Edge-Mount"
  rrect50% 3.18x3.18 hole 1.65: 1(0,2.388)
  body extent -1.59,-5.06 1.59,3.98, height 1.57
NetTie_0402 [mm] "Net Tie 0402 size"
  rect 0.6x0.5 smd paste-0.5: 1(-0.5,0) 2(0.5,0)
  Top Layer region: -0.279,0.203 0.279,0.203 0.279,-0.203 -0.279,-0.203
RAR0016A-MFG [mm]
  round 0.265 smd paste+0 mask-1000: 1(-1.925,2.375) 11(1.925,2.375)
  rrect40% 0.7x0.25 smd paste+0 mask-1000: 2(-2.1,1.825) 3(-2.1,1.325) 4(-2.1,0.825) 8(2.1,0.825) 9(2.1,1.325) 10(2.1,1.825)
  rrect25% 0.8x2.6 smd paste-1000 mask-1000: 5(-2.1,-1.35) 7(2.1,-1.35)
  round 1.813 smd paste-1000 mask-1000: 6(-0.034,0.943)
  rrect40% 0.25x0.7 smd paste+0 mask-1000: 12(0.825,2.6) 13(0.325,2.6) 14(-0.175,2.6) 15(-0.675,2.6) 16(-1.175,2.6)
  Top Layer region: -1.45,1.85 -1.437,1.9 -1.4,1.937 -1.35,1.95 -1.35,1.95 0.9,1.95 0.938,1.942 0.971,1.921 0.992,1.888 1,1.85 1,1.85 1,-2.9 0.987,-2.95 0.95,-2.987 0.9,-3 0.9,-3 -0.9,-3 -0.95,-2.987 -0.987,-2.95 -1,-2.9 -1,-2.9 -1,0.585 -1.004,0.604 -1.015,0.62 -1.031,0.631 -1.05,0.635 -1.05,0.635 -1.35,0.635 -1.388,0.643 -1.421,0.664 -1.442,0.697 -1.45,0.735 -1.45,0.735
  Top Layer region: 2.4,2.2 2.419,2.204 2.435,2.215 2.446,2.231 2.45,2.25 2.45,2.25 2.45,2.4 2.443,2.425 2.425,2.443 2.4,2.45 2.4,2.45 2.1,2.45 2.062,2.458 2.029,2.479 2.008,2.512 2,2.55 2,2.55 2,2.9 1.993,2.925 1.975,2.943 1.95,2.95 1.95,2.95 1.8,2.95 1.775,2.943 1.757,2.925 1.75,2.9 1.75,2.9 1.75,2.25 1.754,2.231 1.765,2.215 1.781,2.204 1.8,2.2 1.8,2.2
  Top Layer region: -2.4,2.2 -2.419,2.204 -2.435,2.215 -2.446,2.231 -2.45,2.25 -2.45,2.25 -2.45,2.4 -2.443,2.425 -2.425,2.443 -2.4,2.45 -2.4,2.45 -2.1,2.45 -2.062,2.458 -2.029,2.479 -2.008,2.512 -2,2.55 -2,2.55 -2,2.9 -1.993,2.925 -1.975,2.943 -1.95,2.95 -1.95,2.95 -1.8,2.95 -1.781,2.946 -1.765,2.935 -1.754,2.919 -1.75,2.9 -1.75,2.9 -1.75,2.25 -1.754,2.231 -1.765,2.215 -1.781,2.204 -1.8,2.2 -1.8,2.2
  silkscreen extent -3.18,-3.1 2.65,3.1, body extent -2.6,-3.1 2.6,3.05, height 0.25
RJA0040A-MFG [mm]
  rrect42% 0.6x0.24 smd paste+0 mask+0: 1(-2.9,2.25) 2(-2.9,1.75) 3(-2.9,1.25) 4(-2.9,0.75) 5(-2.9,0.25) 6(-2.9,-0.25) 7(-2.9,-0.75) 8(-2.9,-1.25) 9(-2.9,-1.75) 10(-2.9,-2.25) 21(2.9,-2.25) 22(2.9,-1.75) 23(2.9,-1.25) 24(2.9,-0.75) 25(2.9,-0.25) 26(2.9,0.25) 27(2.9,0.75) 28(2.9,1.25) 29(2.9,1.75) 30(2.9,2.25)
  rrect42% 0.24x0.6 smd paste+0 mask+0: 11(-2.25,-2.9) 12(-1.75,-2.9) 13(-1.25,-2.9) 14(-0.75,-2.9) 15(-0.25,-2.9) 16(0.25,-2.9) 17(0.75,-2.9) 18(1.25,-2.9) 19(1.75,-2.9) 20(2.25,-2.9) 31(2.25,2.9) 32(1.75,2.9) 33(1.25,2.9) 34(0.75,2.9) 35(0.25,2.9) 36(-0.25,2.9) 37(-0.75,2.9) 38(-1.25,2.9) 39(-1.75,2.9) 40(-2.25,2.9)
  rrect2% 4.15x4.15 smd paste-1000 mask+0: 41(0,0)
  rrect31% 0.32x0.32 smd paste+0 mask+0: A1(-2.74,2.74) A2(-2.74,-2.74) A3(2.74,-2.74) A4(2.74,2.74)
  silkscreen extent -3.87,-3.3 3.3,3.3, body extent -3.3,-3.3 3.3,3.3, height 0.25
TI_Symbol_Overlay_Small [mil]
  silkscreen extent -90,-88 91,88
TP_25MIL-SMT [mil]
  round 25 smd mask-2.5: 1(0,0)
WEEE_Minimum [mil] "WEEElie bin"
  silkscreen extent -95,-172 99,104

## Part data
C1U C3U C4U C5U C8U C10U: library part CMP-0064908-2, "CAP, CERM, 2.2 uF, 6.3 V,+/- 20%, X5R, 0201", Cap_Case=0201, Manufacturer=MuRata, Supplier Part Number 1=490-13225-1-ND, TempCo=X5R, Tolerance_%=20%, Value1=Unknown, Value2=6.3V, ValueDisplayed=2.2uF
C2U C6U C7U C9U C17U: library part CMP-0076713-1, "CAP, CERM, 0.1 µF, 10 V,+/- 10%, X5R, 0201", Cap_Case=0201, Manufacturer="AT Ceramics", TempCo=X5R, Tolerance_%=10%, Value2=10V, ValueDisplayed=0.1µF
C11U C12U: library part CMP-0009661-3, "CAP, CERM, 10 pF, 25 V, +/- 5%, C0G/NP0, 0201", Cap_Case=0201, Manufacturer=MuRata, Supplier Part Number 1=GJM0335C1E100JB01D-ND, TempCo=C0G/NP0, Tolerance_%=5%, Value1=Unknown, Value2=25V, ValueDisplayed=10pF
C13U C43U C45U C46U C48U C49U C82U C88U C90U C91U C95U C96U C135U: library part CMP-0086057-1, "CAP, CERM, 10 pF, 50 V,+/- 5%, C0G/NP0, 0201", Cap_Case=0201, Manufacturer=MuRata, TempCo=C0G/NP0, Tolerance_%=5%, Value2=50V, ValueDisplayed=10pF
C14U C15U: library part CMP-0009752-1, "CAP, CERM, 2200 pF, 16 V, +/- 10%, X7R, 0201", Cap_Case=0201, Manufacturer=MuRata, Supplier Part Number 1=490-3190-1-ND, TempCo=X7R, Tolerance_%=10%, Value1=Unknown, Value2=16V, ValueDisplayed=2200pF
C16U C23U: library part CMP-0009652-3, "CAP, CERM, 220 pF, 50 V, +/- 10%, X7R, AEC-Q200 Grade 1, 0201", Cap_Case=0201_033, Manufacturer=TDK, Supplier Part Number 1=445-12109-1-ND, TempCo=X7R, Tolerance_%=10%, Value1="11.6275 ohm", Value2=50V, ValueDisplayed=220pF
C18U C19U C20U C21U C22U: library part CMP-0009745-1, "CAP, CERM, 1000 pF, 16 V, +/- 10%, X7R, 0201", Cap_Case=0201, Manufacturer=MuRata, Supplier Part Number 1=GRM033R71C102KA01D-ND, TempCo=X7R, Tolerance_%=10%, Value1=Unknown, Value2=16V, ValueDisplayed=1000pF
C24U C25U C38U C74U C85U C128U: library part CMP-0064909-1, "CAP, CERM, 1 uF, 10 V,+/- 20%, X5R, 0201", Cap_Case=0201, Manufacturer=MuRata, Supplier Part Number 1=490-13226-1-ND, TempCo=X5R, Tolerance_%=20%, Value1=Unknown, Value2=10V, ValueDisplayed=1uF
C26U C27U C28U C29U C30U C31U C32U C33U C34U C35U C36U C37U: library part CMP-0098058-1, "4.7 µF ±10% 100V Ceramic Capacitor X5R 0805 (2012 Metric)", Digikey Part Number=445-C2012X5R2A475K125ACCT-ND, Manufacturer=TDK, Mouser Part Number=810-C2012X5R2A475K12, Operating Temperature Range="-55°C to +85°C", TempCo=15%, Temperature Characteristic=X5R, Tolerance_%=10%, ValueDisplayed=4.7uF
C39U C40U C41U C42U C131U C132U C133U C134U: library part CMP-0084680-1, "CAP, CERM, 22 µF, 25 V,+/- 20%, X5R, AEC-Q200 Grade 3, 0805", Cap_Case=0805, Manufacturer=MuRata, TempCo=X5R, Tolerance_%=20%, Value2=25V, ValueDisplayed=22µF
C44U C47U C94U C98U: library part CMP-0006204-2, "CAP, CERM, 0.1 uF, 16 V, +/- 10%, X5R, 0402", Cap_Case=0402, Manufacturer="Johanson Technology", Supplier Part Number 1=709-1129-1-ND, TempCo=X5R, Tolerance_%=10%, Value1=Unknown, Value2=16V, ValueDisplayed=0.1uF
C50U C51U C52U C53U C54U C55U C56U C57U C58U C59U C60U C61U C62U C63U C64U C65U C66U C67U C68U C69U C70U C71U C72U C73U C99U C100U C101U C102U C103U C104U C105U C106U C107U C108U C109U C110U C114U C115U C116U C117U C118U C119U C120U C121U C122U C123U C124U C125U: library part CMP-0001414-1, "Chip Multilayer Ceramic Capacitors for General Purpose, 0402, 2.2uF, X6S, 22%, 20%, 16V", Manufacturer=Murata, Operating Temperature Range="-55°C to +105°C", TempCo=22%, Temperature Characteristic=X6S, Tolerance_%=20%, ValueDisplayed=2.2uF
C75U C76U C77U C78U C79U C80U: library part CMP-0006618-2, "CAP, CERM, 0.1 uF, 100 V, +/- 10%, X5R, 0402", Cap_Case=0402, Manufacturer=MuRata, Supplier Part Number 1=490-10458-1-ND, TempCo=X5R, Tolerance_%=10%, Value1=Unknown, Value2=100V, ValueDisplayed=0.1uF
C81U C83U C84U C86U C87U C89U C92U C93U C97U C111U C112U C113U C126U C127U C129U C130U: library part CMP-0001410-1, "0.22 µF ±10% 25V Ceramic Capacitor U2J 1206 (3216 Metric)", Digikey Part Number=399-16917-1-ND, Manufacturer=KEMET, Mouser Part Number=80-C1206C224K3J, Operating Temperature Range="-55°C to +125°C", TempCo=-750+/-120ppm/°C, Temperature Characteristic=U2J, Tolerance_%=10%, ValueDisplayed=0.22uF
Gnd1U Gnd2U Gnd3U Gnd4U Gnd5U Gnd6U Vin1U Vout1U Vout2U Vout3U Vout4U Vout5U Vout6U: library part CMP-0082316-1, "PCB Pin, 0.04\" DIA, Edge-Mount", Manufacturer=Mill-Max, Supplier Part Number 1=575-3621032150000
J1U: library part CMP-0003661-1, "Like part: FTSH-104-04-L-D-RA", Current_A=3.4A, Digikey Part Number=FTSH-104-04-L-D-RA-ND, Manufacturer=Samtec, Mouser Part Number=200-FTSH10404LDRA, Operating Temperature Range="-55°C to +125°C", Part Number=FTSH-104-04-L-D-RA
L1U L2U L3U L4U: library part CMP-0084501-1, "Inductor, Ferrite Bead, Ferrite, 0.35 A, 0.38 ohm, SMD", Manufacturer=MuRata, Value1="0.38 ohm", Value2=0.35A
Logo1U: library part CMP-0074844-1
Logo2U: library part CMP-0074838-1, "Texas Instrument Corporate Signature"
Logo3U: library part CMP-0074847-1, "FCC_disclaimer"
Logo4U: library part CMP-0074769-1
NT1U: library part CMP-0078142-6, "Single point connection between nets.", Manufacturer=N/A
Q1U Q2U Q3U Q4U Q5U Q6U Q7U Q8U: "40V 1.1mE 90A", Supplier Part Number 1=917-EPC2066TR-ND
R1U: library part CMP-0027472-1, "RES, 1.00, 1%, 0.05 W, 0201", Manufacturer="Yageo America", Power_W=50mW, Supplier Part Number 1=YAG3368CT-ND, TempCo="350 ppm/C", Tolerance_%=1%, Value2=0.05W, Value_Code=1R00, ValueDisplayed=1.00
R2U: library part CMP-0027216-1, "RES, 2.2 k, 5%, 0.05 W, 0201", Manufacturer="Yageo America", Power_W=50mW, Supplier Part Number 1=603-RC0201JR-7D2K2L, TempCo="200 ppm/C", Tolerance_%=5%, Value2=0.05W, Value_Code=2k20, ValueDisplayed=2.2k
R3U R4U: library part CMP-0027896-1, "RES, 845, 1%, 0.05 W, 0201", Manufacturer="Yageo America", Power_W=50mW, Supplier Part Number 1=YAG2820CT-ND, TempCo="200 ppm/C", Tolerance_%=1%, Value2=0.05W, Value_Code=845R, ValueDisplayed=845
R5U R17U: library part CMP-0028084-1, "RES, 1.00 k, 1%, 0.05 W, 0201", Manufacturer="Yageo America", Power_W=50mW, Supplier Part Number 1=603-RC0201FS-7D1KL, TempCo="200 ppm/C", Tolerance_%=1%, Value2=0.05W, Value_Code=1k00, ValueDisplayed=1.00k
R6U: library part CMP-0027186-1, "RES, 10 k, 5%, 0.05 W, 0201", Manufacturer="Yageo America", Power_W=50mW, Supplier Part Number 1=603-RC0201JR-7D10KL, TempCo="200 ppm/C", Tolerance_%=5%, Value2=0.05W, Value_Code=10k0, ValueDisplayed=10k
R7U: library part CMP-0028071-1, "RES, 10.0 k, 1%, 0.05 W, 0201", Manufacturer="Yageo America", Power_W=50mW, Supplier Part Number 1=603-RC0201FS-7D10KL, TempCo="200 ppm/C", Tolerance_%=1%, Value2=0.05W, Value_Code=10k0, ValueDisplayed=10.0k
R8U: library part CMP-0026021-3, "RES, 150 k, 1%, 0.063 W, AEC-Q200 Grade 0, 0402", Manufacturer=Vishay-Dale, Power_W=63mW, Supplier Part Number 1=541-150KLCT-ND, TempCo="100 ppm/C", Tolerance_%=1%, Value2=0.063W, Value_Code=150k
R9U R10U: library part CMP-0027260-1, "RES, 10 k, 5%, 0.05 W, 0201", Manufacturer="Yageo America", Power_W=50mW, Supplier Part Number 1=603-RC0201JS-7D10KL, TempCo="200 ppm/C", Tolerance_%=5%, Value2=0.05W, Value_Code=10k0, ValueDisplayed=10k
R11U R13U: library part CMP-0860046-1, "RES, 14.0 k, 1%, 0.0625 W, 0402", Manufacturer=Yageo, Power_W=62.5mW, Supplier Part Number 1=311-14.0KLRCT-ND, TempCo="100 ppm/C", Tolerance_%=1%, Value2=0.0625W, Value_Code=14k0, ValueDisplayed=14.0k
R12U: library part CMP-0028092-1, "RES, 24.3, 1%, 0.05 W, 0201", Manufacturer="Yageo America", Power_W=50mW, Supplier Part Number 1=603-RC0201FS-7D24R3L, TempCo="200 ppm/C", Tolerance_%=1%, Value2=0.05W, Value_Code=24R3, ValueDisplayed=24.3
R14U R15U: library part CMP-0028149-1, "RES, 1.00 k, 0.5%, 0.05 W, 0201", Manufacturer="Yageo America", Power_W=50mW, Supplier Part Number 1=RC0201DR-071KL-ND, TempCo="200 ppm/C", Tolerance_%=0.5%, Value2=0.05W, Value_Code=1k00, ValueDisplayed=1.00k
R16U: library part CMP-0028221-1, "RES, 4.70 k, 0.5%, 0.05 W, 0201", Manufacturer="Yageo America", Power_W=50mW, Supplier Part Number 1=RC0201DR-074K7L-ND, TempCo="200 ppm/C", Tolerance_%=0.5%, Value2=0.05W, Value_Code=4k70, ValueDisplayed=4.70k
R18U: library part CMP-0027788-1, "RES, 5.11 k, 1%, 0.05 W, 0201", Manufacturer="Yageo America", Power_W=50mW, Supplier Part Number 1=YAG2740CT-ND, TempCo="200 ppm/C", Tolerance_%=1%, Value2=0.05W, Value_Code=5k11, ValueDisplayed=5.11k
R19U R28U R33U R42U: library part CMP-0078192-2, "RES, 20.0, 1%, 0.05 W, 0201", Manufacturer=Vishay-Dale, Power_W=50mW, Supplier Part Number 1=541-2947-1-ND, TempCo="200 ppm/C", Tolerance_%=1%, Value2=0.05W, Value_Code=20R0, ValueDisplayed=20.0
R20U R29U R34U R43U: library part CMP-0028072-1, "RES, 10.0, 1%, 0.05 W, 0201", Manufacturer="Yageo America", Power_W=50mW, Supplier Part Number 1=603-RC0201FS-7D10RL, TempCo="350 ppm/C", Tolerance_%=1%, Value2=0.05W, Value_Code=10R0, ValueDisplayed=10.0
R21U R30U R35U R44U: library part CMP-0028226-1, "RES, 5.11 k, 0.5%, 0.05 W, 0201", Manufacturer="Yageo America", Power_W=50mW, Supplier Part Number 1=RC0201DR-075K11L-ND, TempCo="200 ppm/C", Tolerance_%=0.5%, Value2=0.05W, Value_Code=5k11, ValueDisplayed=5.11k
R22U R23U R31U R32U R36U R39U R45U R46U: library part CMP-0086442-2, "RES SMD 0 OHM JUMPER 1/20W 0201", Manufacturer=Yageo, Power_W=50mW, TempCo=200ppm/°C, Tolerance_%=5%
R24U R25U R26U R27U R37U R38U R40U R41U: library part CMP-0028098-1, "RES, 2.00, 1%, 0.05 W, 0201", Manufacturer="Yageo America", Power_W=50mW, Supplier Part Number 1=603-RC0201FS-7D2RL, TempCo="350 ppm/C", Tolerance_%=1%, Value2=0.05W, Value_Code=2R00, ValueDisplayed=2.00
RT1U RT2U: library part CMP-0084565-1, "Thermistor, DEC0002A (X1SON-2)", Alternate Manufacturer="Texas Instruments", Alternate PartNumber=TMP6131DECR
TP1U TP2U TP3U TP4U TP5U TP6U TP7U TP8U TP9U TP10U TP11U TP12U TP13U TP14U TP15U: library part CMP-0078143-3, "TEST POINT.  No entry in BOM.", Manufacturer=N/A
U1U: library part CMP-0030785-1, "UCD3138A Highly Integrated Digital Controller for Isolated Power 40-VQFN -40 to 125", Digikey Part Number=296-45070-1-ND, Manufacturer="Texas Instruments", Max Supply Voltage=3.6V, Min Supply Voltage=1.6V, Mouser Part Number=595-UCD3138ARJAT, Nominal Supply Current=105mA, Operating Temperature Range="-40°C to +125°C"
